Omron CX-Programmer project 新工程 (CX-Programmer 9.31)

# PLC 新PLC1: CP1E E10

## Global symbols (name address type ; comment)
0.00 BOOL  ; 输入
0.01 BOOL  ; 传感器触发正信号
0.02 BOOL  ; 复位
0.03 BOOL  ; 转盘工位传感器信号
100.00 BOOL  ; 相机触发信号
100.01 BOOL  ; 光源触发
100.02 BOOL  ; 剔除信号
100.03 BOOL  ; 设备停止1
D2 CHANNEL  ; 气缸1剔除延时调整
D8 CHANNEL  ; 气缸1剔除延时调整

## Program 新程序1 (cyclic task 0)

### Section 延时设置

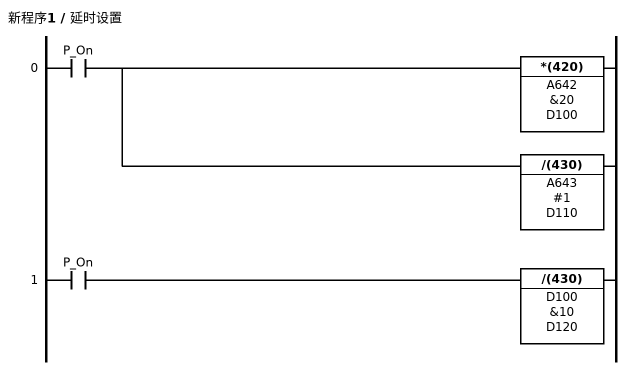
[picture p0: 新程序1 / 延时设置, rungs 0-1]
; rung 0
LD P_On
*(420) A642 &20 D100
/(430) A643 #1 D110
; rung 1
LD P_On
/(430) D100 &10 D120

### Section 相机触发

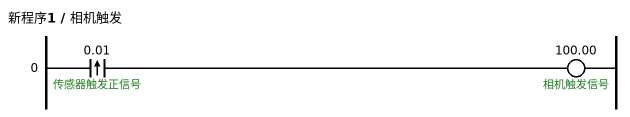
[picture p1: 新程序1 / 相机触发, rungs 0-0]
; rung 0
@LD 0.01  ; 传感器触发正信号
OUT 100.00  ; 相机触发信号

### Section 错误记忆

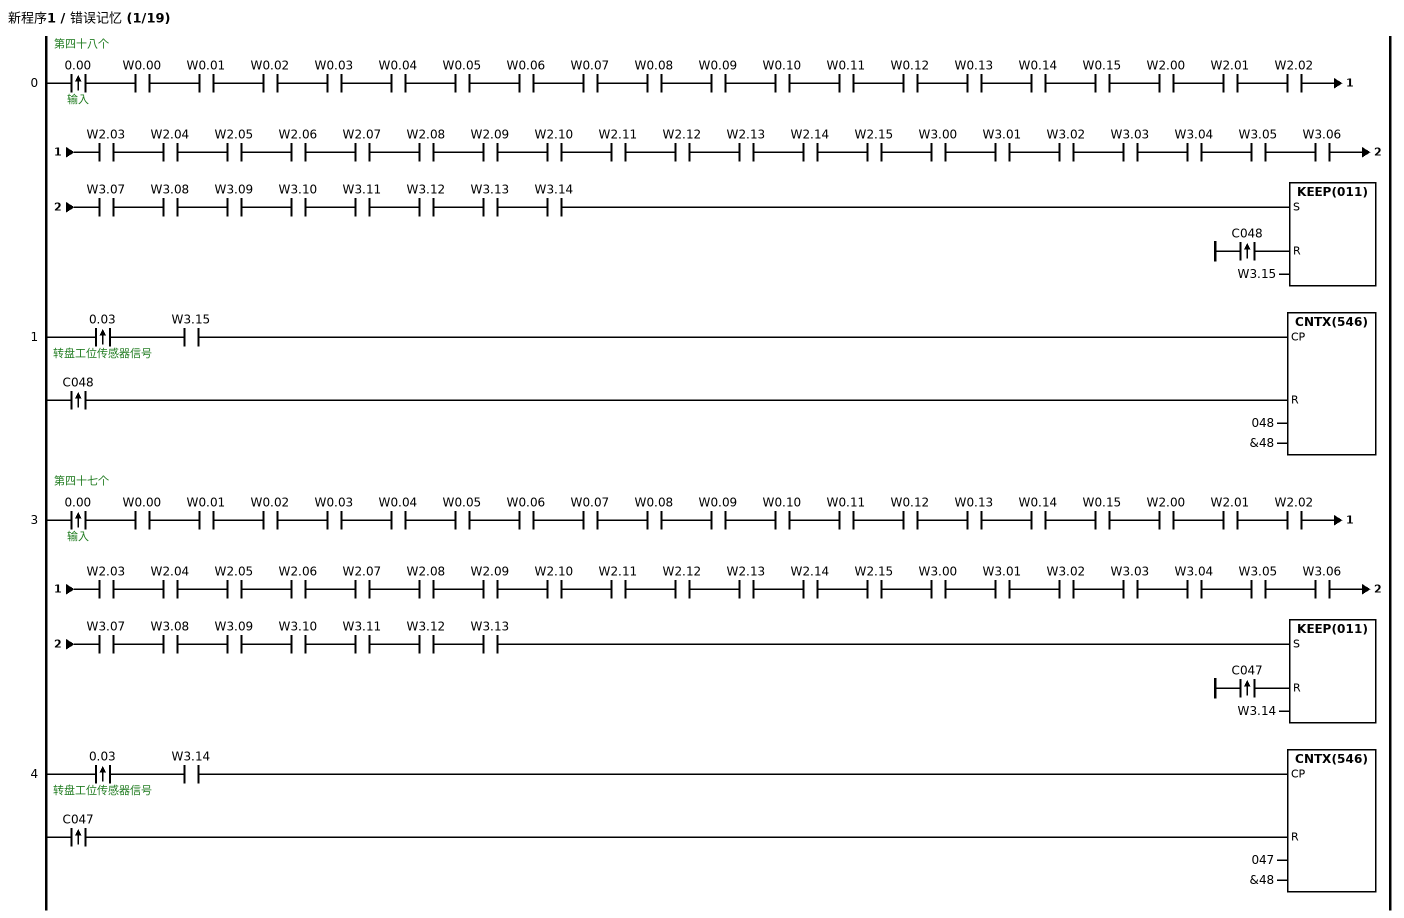
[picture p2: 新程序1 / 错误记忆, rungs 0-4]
; rung 0: 第四十八个
@LD 0.00  ; 输入
AND W0.00
AND W0.01
AND W0.02
AND W0.03
AND W0.04
AND W0.05
AND W0.06
AND W0.07
AND W0.08
AND W0.09
AND W0.10
AND W0.11
AND W0.12
AND W0.13
AND W0.14
AND W0.15
AND W2.00
AND W2.01
AND W2.02
AND W2.03
AND W2.04
AND W2.05
AND W2.06
AND W2.07
AND W2.08
AND W2.09
AND W2.10
AND W2.11
AND W2.12
AND W2.13
AND W2.14
AND W2.15
AND W3.00
AND W3.01
AND W3.02
AND W3.03
AND W3.04
AND W3.05
AND W3.06
AND W3.07
AND W3.08
AND W3.09
AND W3.10
AND W3.11
AND W3.12
AND W3.13
AND W3.14
@LD C048
KEEP(011) W3.15
; rung 1
@LD 0.03  ; 转盘工位传感器信号
AND W3.15
@LD C048
CNTX(546) 048 &48
; rung 3: 第四十七个
@LD 0.00  ; 输入
AND W0.00
AND W0.01
AND W0.02
AND W0.03
AND W0.04
AND W0.05
AND W0.06
AND W0.07
AND W0.08
AND W0.09
AND W0.10
AND W0.11
AND W0.12
AND W0.13
AND W0.14
AND W0.15
AND W2.00
AND W2.01
AND W2.02
AND W2.03
AND W2.04
AND W2.05
AND W2.06
AND W2.07
AND W2.08
AND W2.09
AND W2.10
AND W2.11
AND W2.12
AND W2.13
AND W2.14
AND W2.15
AND W3.00
AND W3.01
AND W3.02
AND W3.03
AND W3.04
AND W3.05
AND W3.06
AND W3.07
AND W3.08
AND W3.09
AND W3.10
AND W3.11
AND W3.12
AND W3.13
@LD C047
KEEP(011) W3.14
; rung 4
@LD 0.03  ; 转盘工位传感器信号
AND W3.14
@LD C047
CNTX(546) 047 &48

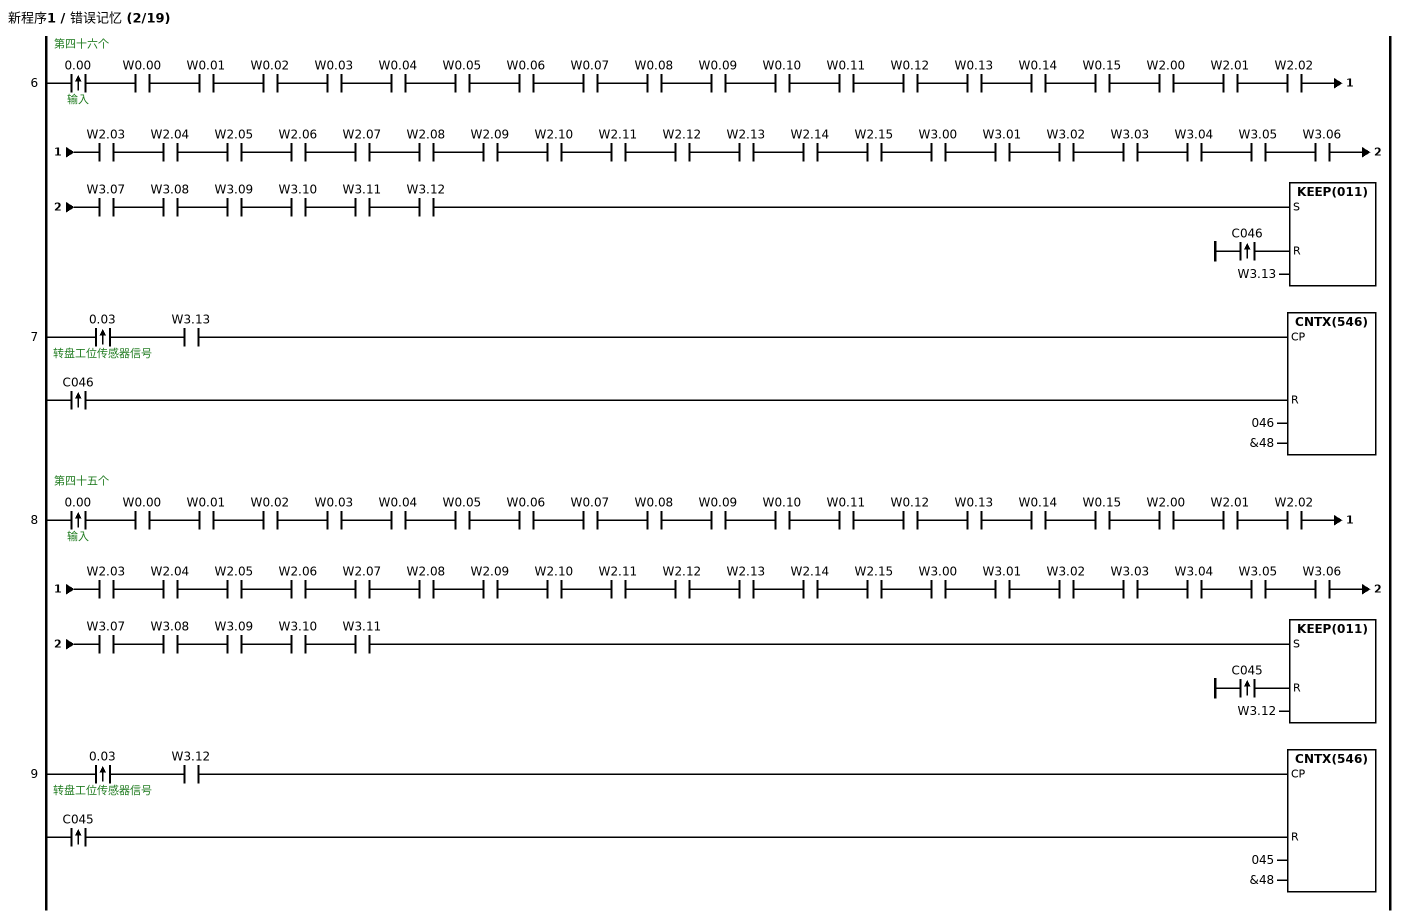
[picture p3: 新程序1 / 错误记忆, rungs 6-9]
; rung 6: 第四十六个
@LD 0.00  ; 输入
AND W0.00
AND W0.01
AND W0.02
AND W0.03
AND W0.04
AND W0.05
AND W0.06
AND W0.07
AND W0.08
AND W0.09
AND W0.10
AND W0.11
AND W0.12
AND W0.13
AND W0.14
AND W0.15
AND W2.00
AND W2.01
AND W2.02
AND W2.03
AND W2.04
AND W2.05
AND W2.06
AND W2.07
AND W2.08
AND W2.09
AND W2.10
AND W2.11
AND W2.12
AND W2.13
AND W2.14
AND W2.15
AND W3.00
AND W3.01
AND W3.02
AND W3.03
AND W3.04
AND W3.05
AND W3.06
AND W3.07
AND W3.08
AND W3.09
AND W3.10
AND W3.11
AND W3.12
@LD C046
KEEP(011) W3.13
; rung 7
@LD 0.03  ; 转盘工位传感器信号
AND W3.13
@LD C046
CNTX(546) 046 &48
; rung 8: 第四十五个
@LD 0.00  ; 输入
AND W0.00
AND W0.01
AND W0.02
AND W0.03
AND W0.04
AND W0.05
AND W0.06
AND W0.07
AND W0.08
AND W0.09
AND W0.10
AND W0.11
AND W0.12
AND W0.13
AND W0.14
AND W0.15
AND W2.00
AND W2.01
AND W2.02
AND W2.03
AND W2.04
AND W2.05
AND W2.06
AND W2.07
AND W2.08
AND W2.09
AND W2.10
AND W2.11
AND W2.12
AND W2.13
AND W2.14
AND W2.15
AND W3.00
AND W3.01
AND W3.02
AND W3.03
AND W3.04
AND W3.05
AND W3.06
AND W3.07
AND W3.08
AND W3.09
AND W3.10
AND W3.11
@LD C045
KEEP(011) W3.12
; rung 9
@LD 0.03  ; 转盘工位传感器信号
AND W3.12
@LD C045
CNTX(546) 045 &48

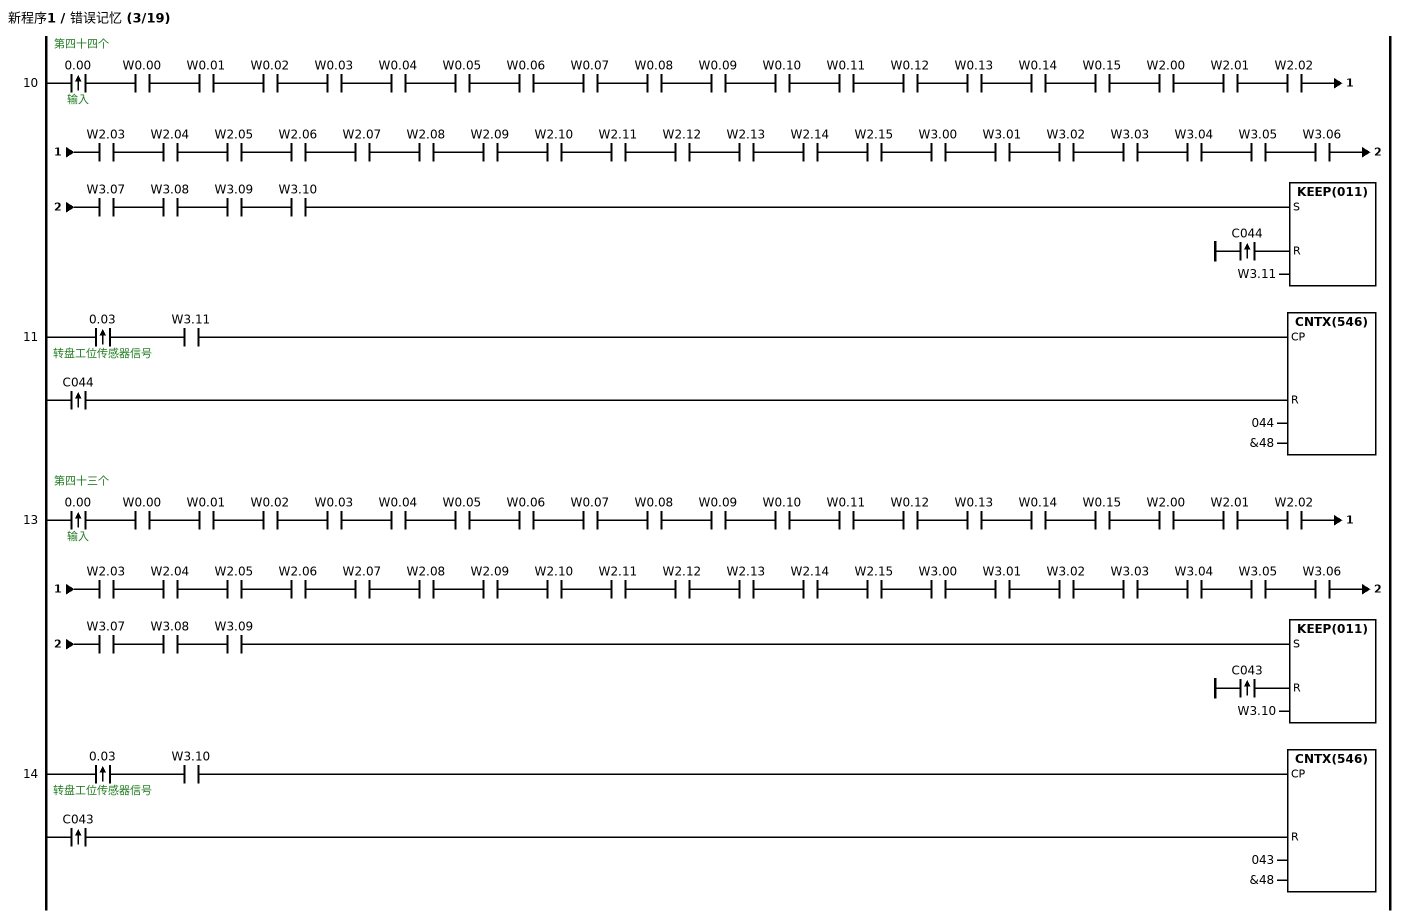
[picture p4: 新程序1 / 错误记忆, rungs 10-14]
; rung 10: 第四十四个
@LD 0.00  ; 输入
AND W0.00
AND W0.01
AND W0.02
AND W0.03
AND W0.04
AND W0.05
AND W0.06
AND W0.07
AND W0.08
AND W0.09
AND W0.10
AND W0.11
AND W0.12
AND W0.13
AND W0.14
AND W0.15
AND W2.00
AND W2.01
AND W2.02
AND W2.03
AND W2.04
AND W2.05
AND W2.06
AND W2.07
AND W2.08
AND W2.09
AND W2.10
AND W2.11
AND W2.12
AND W2.13
AND W2.14
AND W2.15
AND W3.00
AND W3.01
AND W3.02
AND W3.03
AND W3.04
AND W3.05
AND W3.06
AND W3.07
AND W3.08
AND W3.09
AND W3.10
@LD C044
KEEP(011) W3.11
; rung 11
@LD 0.03  ; 转盘工位传感器信号
AND W3.11
@LD C044
CNTX(546) 044 &48
; rung 13: 第四十三个
@LD 0.00  ; 输入
AND W0.00
AND W0.01
AND W0.02
AND W0.03
AND W0.04
AND W0.05
AND W0.06
AND W0.07
AND W0.08
AND W0.09
AND W0.10
AND W0.11
AND W0.12
AND W0.13
AND W0.14
AND W0.15
AND W2.00
AND W2.01
AND W2.02
AND W2.03
AND W2.04
AND W2.05
AND W2.06
AND W2.07
AND W2.08
AND W2.09
AND W2.10
AND W2.11
AND W2.12
AND W2.13
AND W2.14
AND W2.15
AND W3.00
AND W3.01
AND W3.02
AND W3.03
AND W3.04
AND W3.05
AND W3.06
AND W3.07
AND W3.08
AND W3.09
@LD C043
KEEP(011) W3.10
; rung 14
@LD 0.03  ; 转盘工位传感器信号
AND W3.10
@LD C043
CNTX(546) 043 &48

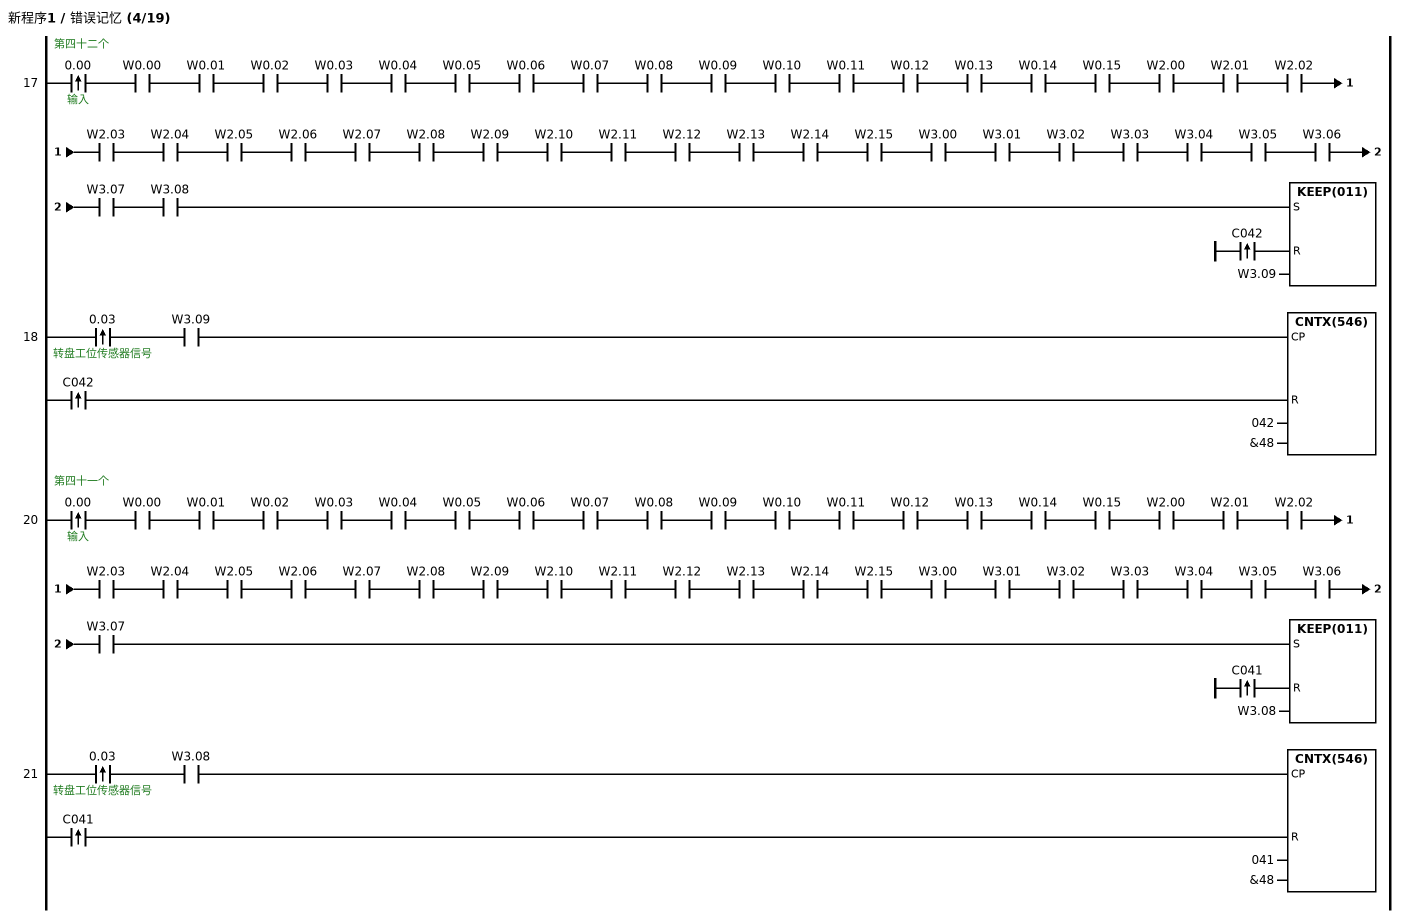
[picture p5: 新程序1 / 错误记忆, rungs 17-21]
; rung 17: 第四十二个
@LD 0.00  ; 输入
AND W0.00
AND W0.01
AND W0.02
AND W0.03
AND W0.04
AND W0.05
AND W0.06
AND W0.07
AND W0.08
AND W0.09
AND W0.10
AND W0.11
AND W0.12
AND W0.13
AND W0.14
AND W0.15
AND W2.00
AND W2.01
AND W2.02
AND W2.03
AND W2.04
AND W2.05
AND W2.06
AND W2.07
AND W2.08
AND W2.09
AND W2.10
AND W2.11
AND W2.12
AND W2.13
AND W2.14
AND W2.15
AND W3.00
AND W3.01
AND W3.02
AND W3.03
AND W3.04
AND W3.05
AND W3.06
AND W3.07
AND W3.08
@LD C042
KEEP(011) W3.09
; rung 18
@LD 0.03  ; 转盘工位传感器信号
AND W3.09
@LD C042
CNTX(546) 042 &48
; rung 20: 第四十一个
@LD 0.00  ; 输入
AND W0.00
AND W0.01
AND W0.02
AND W0.03
AND W0.04
AND W0.05
AND W0.06
AND W0.07
AND W0.08
AND W0.09
AND W0.10
AND W0.11
AND W0.12
AND W0.13
AND W0.14
AND W0.15
AND W2.00
AND W2.01
AND W2.02
AND W2.03
AND W2.04
AND W2.05
AND W2.06
AND W2.07
AND W2.08
AND W2.09
AND W2.10
AND W2.11
AND W2.12
AND W2.13
AND W2.14
AND W2.15
AND W3.00
AND W3.01
AND W3.02
AND W3.03
AND W3.04
AND W3.05
AND W3.06
AND W3.07
@LD C041
KEEP(011) W3.08
; rung 21
@LD 0.03  ; 转盘工位传感器信号
AND W3.08
@LD C041
CNTX(546) 041 &48

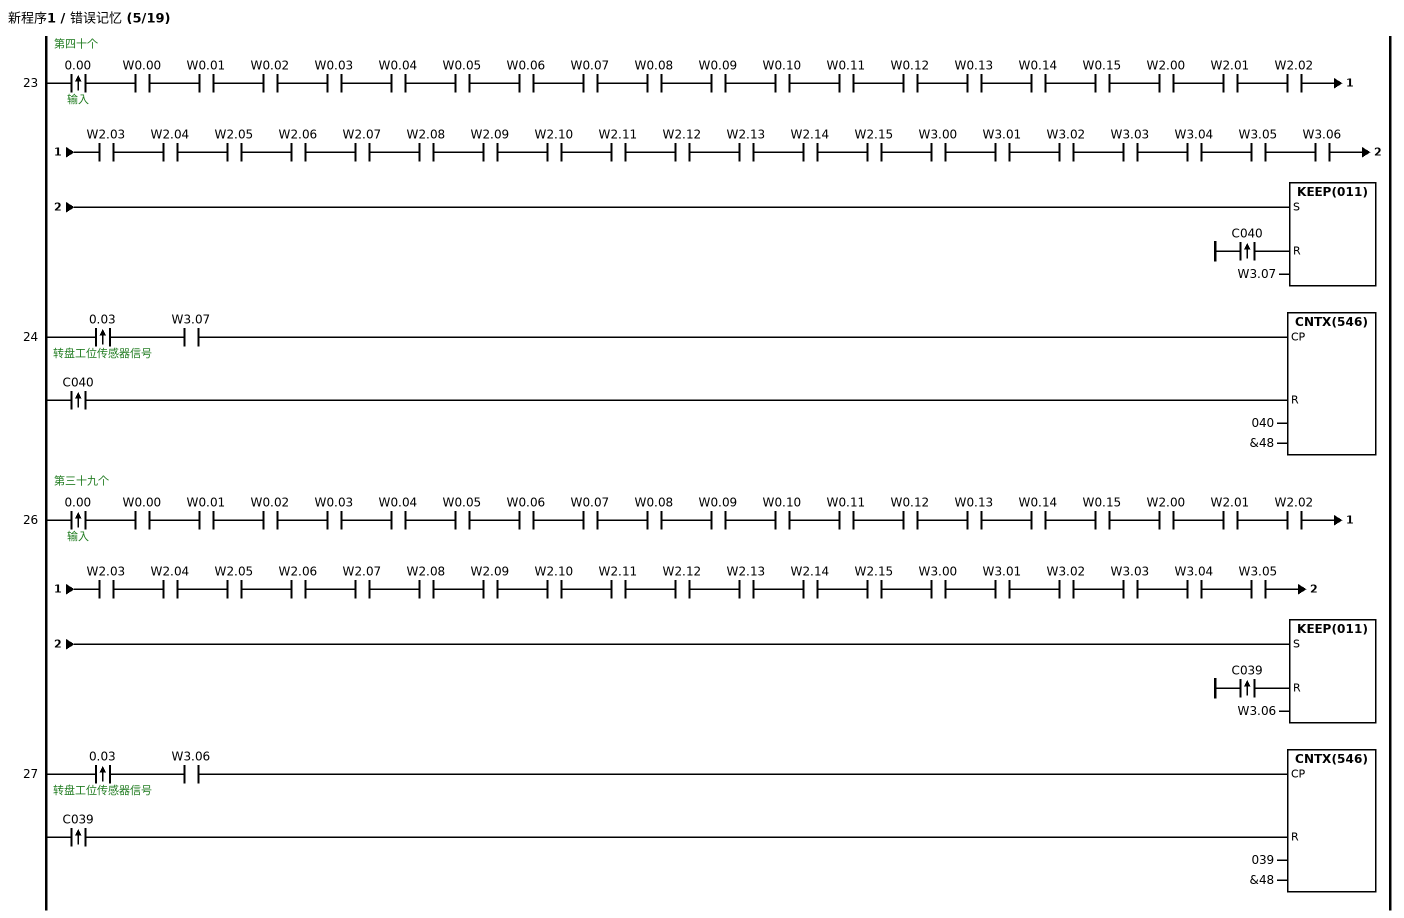
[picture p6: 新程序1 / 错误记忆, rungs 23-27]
; rung 23: 第四十个
@LD 0.00  ; 输入
AND W0.00
AND W0.01
AND W0.02
AND W0.03
AND W0.04
AND W0.05
AND W0.06
AND W0.07
AND W0.08
AND W0.09
AND W0.10
AND W0.11
AND W0.12
AND W0.13
AND W0.14
AND W0.15
AND W2.00
AND W2.01
AND W2.02
AND W2.03
AND W2.04
AND W2.05
AND W2.06
AND W2.07
AND W2.08
AND W2.09
AND W2.10
AND W2.11
AND W2.12
AND W2.13
AND W2.14
AND W2.15
AND W3.00
AND W3.01
AND W3.02
AND W3.03
AND W3.04
AND W3.05
AND W3.06
@LD C040
KEEP(011) W3.07
; rung 24
@LD 0.03  ; 转盘工位传感器信号
AND W3.07
@LD C040
CNTX(546) 040 &48
; rung 26: 第三十九个
@LD 0.00  ; 输入
AND W0.00
AND W0.01
AND W0.02
AND W0.03
AND W0.04
AND W0.05
AND W0.06
AND W0.07
AND W0.08
AND W0.09
AND W0.10
AND W0.11
AND W0.12
AND W0.13
AND W0.14
AND W0.15
AND W2.00
AND W2.01
AND W2.02
AND W2.03
AND W2.04
AND W2.05
AND W2.06
AND W2.07
AND W2.08
AND W2.09
AND W2.10
AND W2.11
AND W2.12
AND W2.13
AND W2.14
AND W2.15
AND W3.00
AND W3.01
AND W3.02
AND W3.03
AND W3.04
AND W3.05
@LD C039
KEEP(011) W3.06
; rung 27
@LD 0.03  ; 转盘工位传感器信号
AND W3.06
@LD C039
CNTX(546) 039 &48

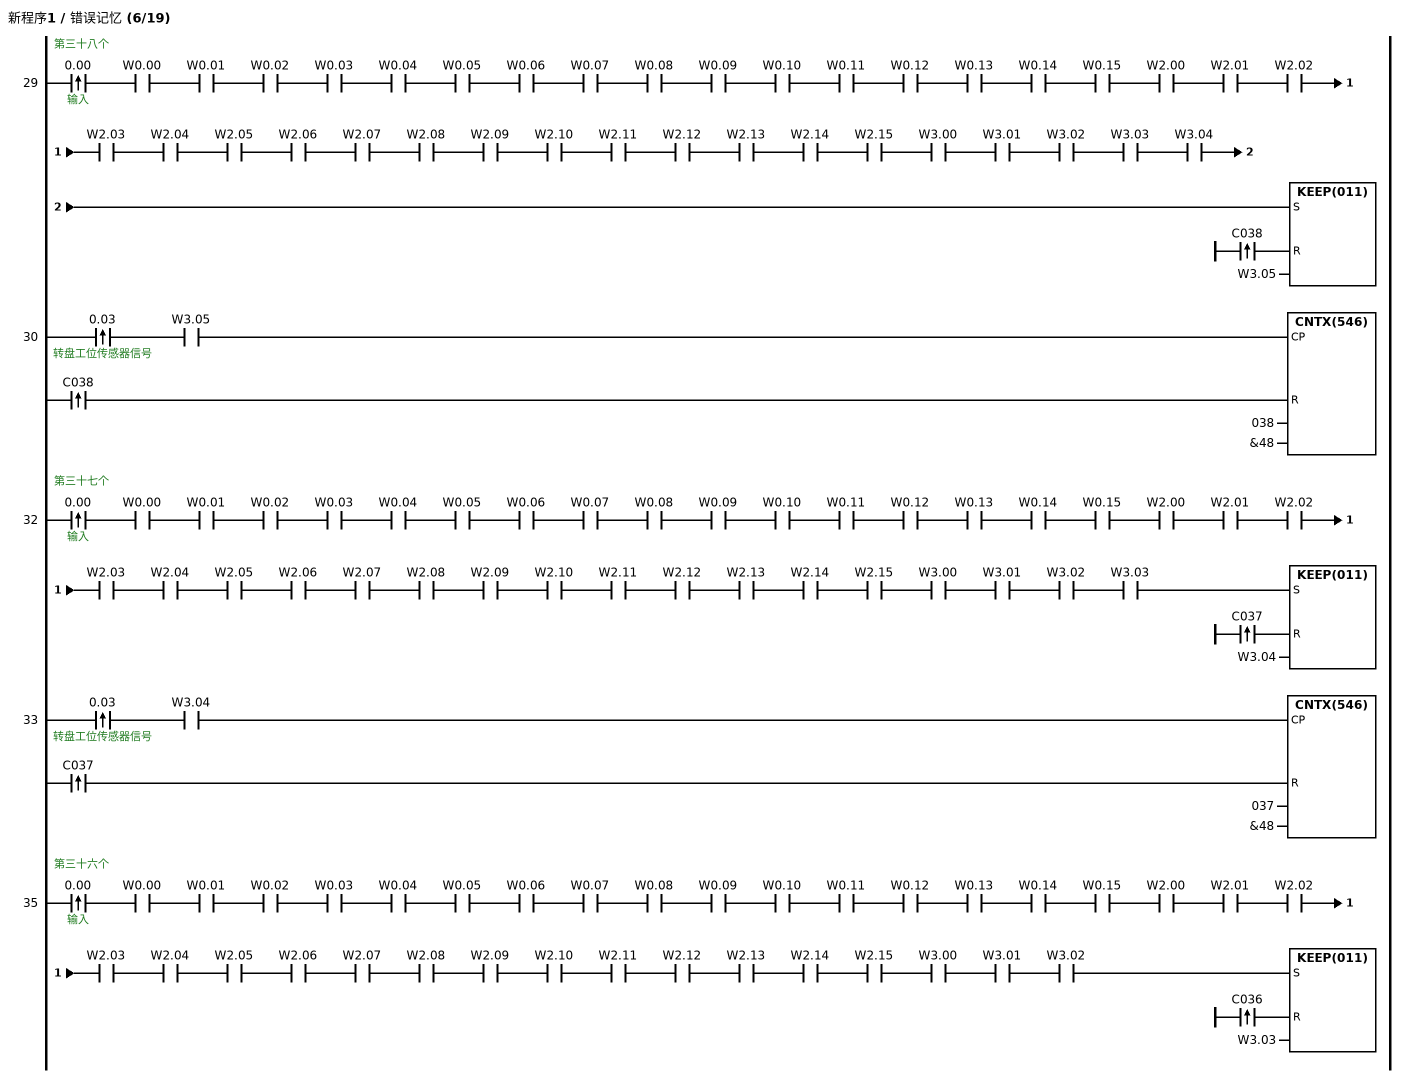
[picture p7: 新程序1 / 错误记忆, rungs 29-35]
; rung 29: 第三十八个
@LD 0.00  ; 输入
AND W0.00
AND W0.01
AND W0.02
AND W0.03
AND W0.04
AND W0.05
AND W0.06
AND W0.07
AND W0.08
AND W0.09
AND W0.10
AND W0.11
AND W0.12
AND W0.13
AND W0.14
AND W0.15
AND W2.00
AND W2.01
AND W2.02
AND W2.03
AND W2.04
AND W2.05
AND W2.06
AND W2.07
AND W2.08
AND W2.09
AND W2.10
AND W2.11
AND W2.12
AND W2.13
AND W2.14
AND W2.15
AND W3.00
AND W3.01
AND W3.02
AND W3.03
AND W3.04
@LD C038
KEEP(011) W3.05
; rung 30
@LD 0.03  ; 转盘工位传感器信号
AND W3.05
@LD C038
CNTX(546) 038 &48
; rung 32: 第三十七个
@LD 0.00  ; 输入
AND W0.00
AND W0.01
AND W0.02
AND W0.03
AND W0.04
AND W0.05
AND W0.06
AND W0.07
AND W0.08
AND W0.09
AND W0.10
AND W0.11
AND W0.12
AND W0.13
AND W0.14
AND W0.15
AND W2.00
AND W2.01
AND W2.02
AND W2.03
AND W2.04
AND W2.05
AND W2.06
AND W2.07
AND W2.08
AND W2.09
AND W2.10
AND W2.11
AND W2.12
AND W2.13
AND W2.14
AND W2.15
AND W3.00
AND W3.01
AND W3.02
AND W3.03
@LD C037
KEEP(011) W3.04
; rung 33
@LD 0.03  ; 转盘工位传感器信号
AND W3.04
@LD C037
CNTX(546) 037 &48
; rung 35: 第三十六个
@LD 0.00  ; 输入
AND W0.00
AND W0.01
AND W0.02
AND W0.03
AND W0.04
AND W0.05
AND W0.06
AND W0.07
AND W0.08
AND W0.09
AND W0.10
AND W0.11
AND W0.12
AND W0.13
AND W0.14
AND W0.15
AND W2.00
AND W2.01
AND W2.02
AND W2.03
AND W2.04
AND W2.05
AND W2.06
AND W2.07
AND W2.08
AND W2.09
AND W2.10
AND W2.11
AND W2.12
AND W2.13
AND W2.14
AND W2.15
AND W3.00
AND W3.01
AND W3.02
@LD C036
KEEP(011) W3.03

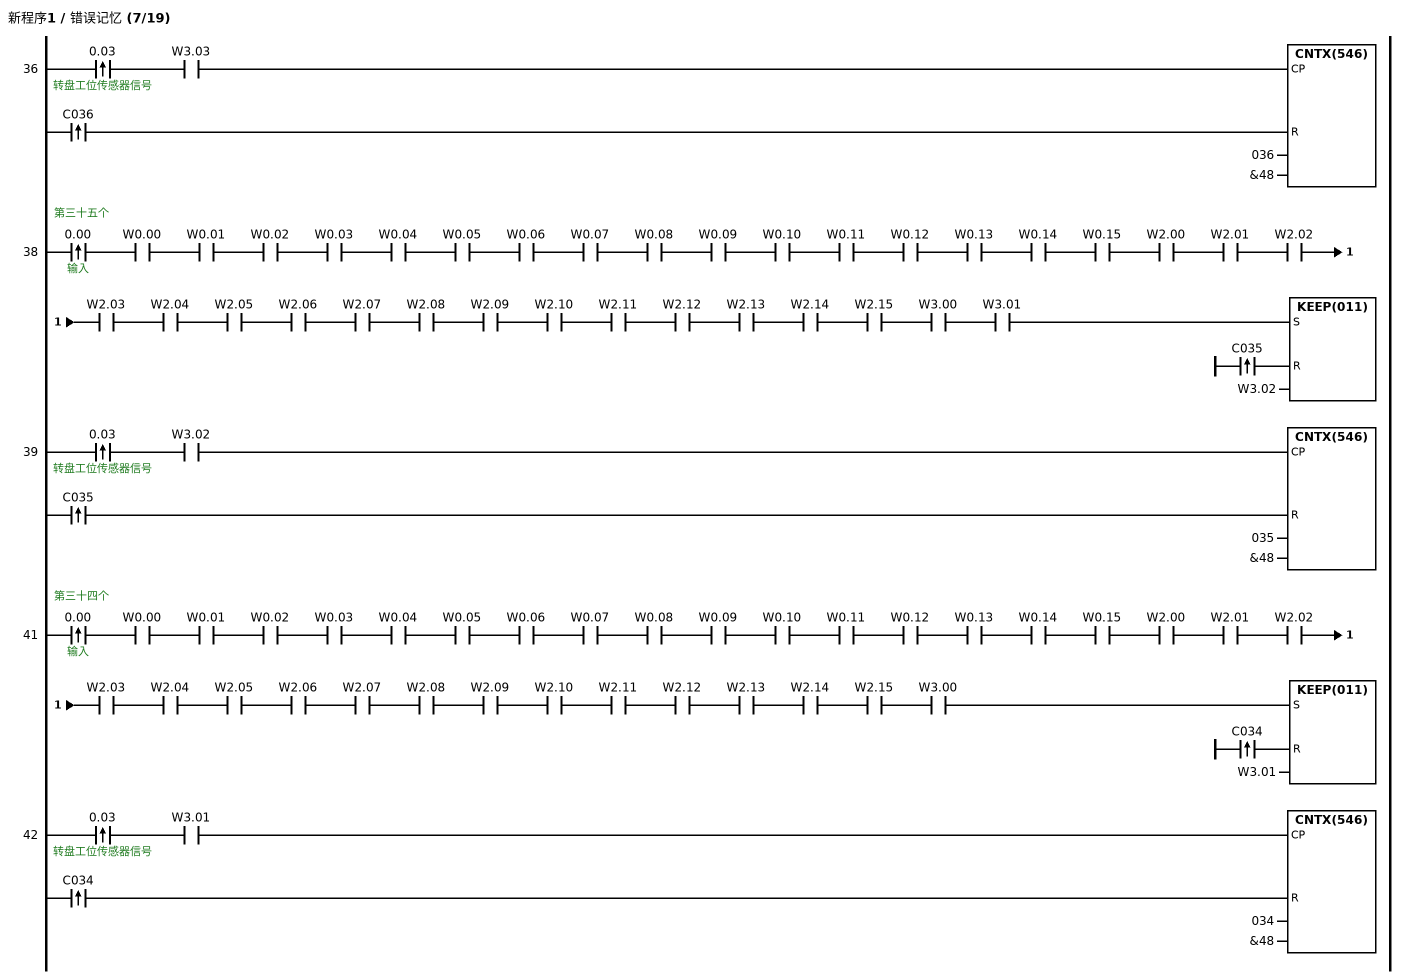
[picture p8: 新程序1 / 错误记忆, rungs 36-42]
; rung 36
@LD 0.03  ; 转盘工位传感器信号
AND W3.03
@LD C036
CNTX(546) 036 &48
; rung 38: 第三十五个
@LD 0.00  ; 输入
AND W0.00
AND W0.01
AND W0.02
AND W0.03
AND W0.04
AND W0.05
AND W0.06
AND W0.07
AND W0.08
AND W0.09
AND W0.10
AND W0.11
AND W0.12
AND W0.13
AND W0.14
AND W0.15
AND W2.00
AND W2.01
AND W2.02
AND W2.03
AND W2.04
AND W2.05
AND W2.06
AND W2.07
AND W2.08
AND W2.09
AND W2.10
AND W2.11
AND W2.12
AND W2.13
AND W2.14
AND W2.15
AND W3.00
AND W3.01
@LD C035
KEEP(011) W3.02
; rung 39
@LD 0.03  ; 转盘工位传感器信号
AND W3.02
@LD C035
CNTX(546) 035 &48
; rung 41: 第三十四个
@LD 0.00  ; 输入
AND W0.00
AND W0.01
AND W0.02
AND W0.03
AND W0.04
AND W0.05
AND W0.06
AND W0.07
AND W0.08
AND W0.09
AND W0.10
AND W0.11
AND W0.12
AND W0.13
AND W0.14
AND W0.15
AND W2.00
AND W2.01
AND W2.02
AND W2.03
AND W2.04
AND W2.05
AND W2.06
AND W2.07
AND W2.08
AND W2.09
AND W2.10
AND W2.11
AND W2.12
AND W2.13
AND W2.14
AND W2.15
AND W3.00
@LD C034
KEEP(011) W3.01
; rung 42
@LD 0.03  ; 转盘工位传感器信号
AND W3.01
@LD C034
CNTX(546) 034 &48

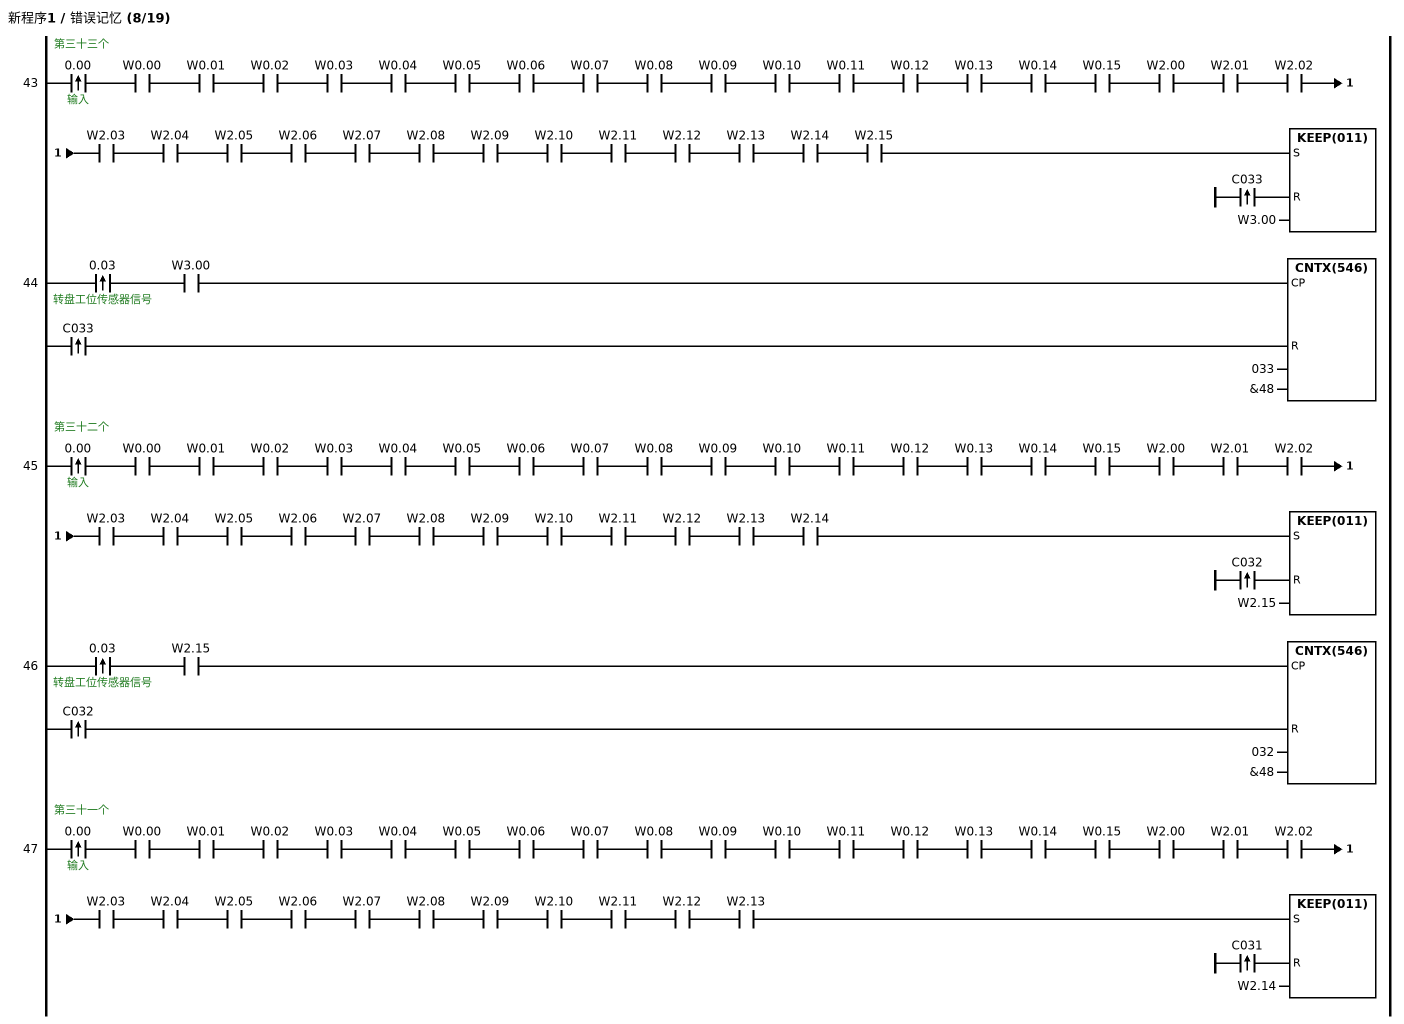
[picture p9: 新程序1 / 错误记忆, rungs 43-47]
; rung 43: 第三十三个
@LD 0.00  ; 输入
AND W0.00
AND W0.01
AND W0.02
AND W0.03
AND W0.04
AND W0.05
AND W0.06
AND W0.07
AND W0.08
AND W0.09
AND W0.10
AND W0.11
AND W0.12
AND W0.13
AND W0.14
AND W0.15
AND W2.00
AND W2.01
AND W2.02
AND W2.03
AND W2.04
AND W2.05
AND W2.06
AND W2.07
AND W2.08
AND W2.09
AND W2.10
AND W2.11
AND W2.12
AND W2.13
AND W2.14
AND W2.15
@LD C033
KEEP(011) W3.00
; rung 44
@LD 0.03  ; 转盘工位传感器信号
AND W3.00
@LD C033
CNTX(546) 033 &48
; rung 45: 第三十二个
@LD 0.00  ; 输入
AND W0.00
AND W0.01
AND W0.02
AND W0.03
AND W0.04
AND W0.05
AND W0.06
AND W0.07
AND W0.08
AND W0.09
AND W0.10
AND W0.11
AND W0.12
AND W0.13
AND W0.14
AND W0.15
AND W2.00
AND W2.01
AND W2.02
AND W2.03
AND W2.04
AND W2.05
AND W2.06
AND W2.07
AND W2.08
AND W2.09
AND W2.10
AND W2.11
AND W2.12
AND W2.13
AND W2.14
@LD C032
KEEP(011) W2.15
; rung 46
@LD 0.03  ; 转盘工位传感器信号
AND W2.15
@LD C032
CNTX(546) 032 &48
; rung 47: 第三十一个
@LD 0.00  ; 输入
AND W0.00
AND W0.01
AND W0.02
AND W0.03
AND W0.04
AND W0.05
AND W0.06
AND W0.07
AND W0.08
AND W0.09
AND W0.10
AND W0.11
AND W0.12
AND W0.13
AND W0.14
AND W0.15
AND W2.00
AND W2.01
AND W2.02
AND W2.03
AND W2.04
AND W2.05
AND W2.06
AND W2.07
AND W2.08
AND W2.09
AND W2.10
AND W2.11
AND W2.12
AND W2.13
@LD C031
KEEP(011) W2.14

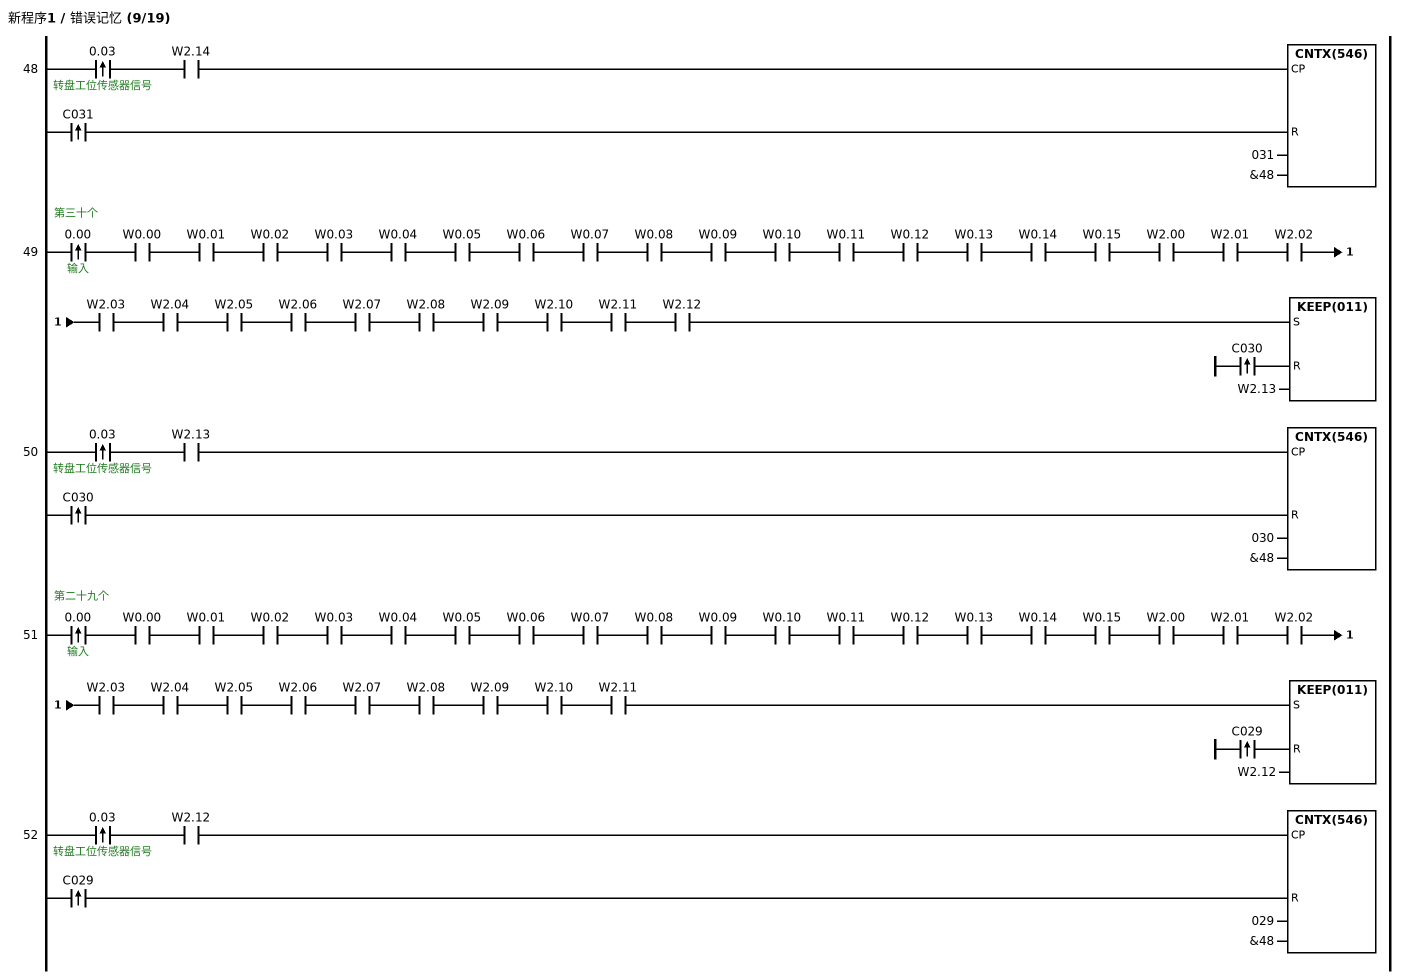
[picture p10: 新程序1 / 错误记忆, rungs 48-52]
; rung 48
@LD 0.03  ; 转盘工位传感器信号
AND W2.14
@LD C031
CNTX(546) 031 &48
; rung 49: 第三十个
@LD 0.00  ; 输入
AND W0.00
AND W0.01
AND W0.02
AND W0.03
AND W0.04
AND W0.05
AND W0.06
AND W0.07
AND W0.08
AND W0.09
AND W0.10
AND W0.11
AND W0.12
AND W0.13
AND W0.14
AND W0.15
AND W2.00
AND W2.01
AND W2.02
AND W2.03
AND W2.04
AND W2.05
AND W2.06
AND W2.07
AND W2.08
AND W2.09
AND W2.10
AND W2.11
AND W2.12
@LD C030
KEEP(011) W2.13
; rung 50
@LD 0.03  ; 转盘工位传感器信号
AND W2.13
@LD C030
CNTX(546) 030 &48
; rung 51: 第二十九个
@LD 0.00  ; 输入
AND W0.00
AND W0.01
AND W0.02
AND W0.03
AND W0.04
AND W0.05
AND W0.06
AND W0.07
AND W0.08
AND W0.09
AND W0.10
AND W0.11
AND W0.12
AND W0.13
AND W0.14
AND W0.15
AND W2.00
AND W2.01
AND W2.02
AND W2.03
AND W2.04
AND W2.05
AND W2.06
AND W2.07
AND W2.08
AND W2.09
AND W2.10
AND W2.11
@LD C029
KEEP(011) W2.12
; rung 52
@LD 0.03  ; 转盘工位传感器信号
AND W2.12
@LD C029
CNTX(546) 029 &48

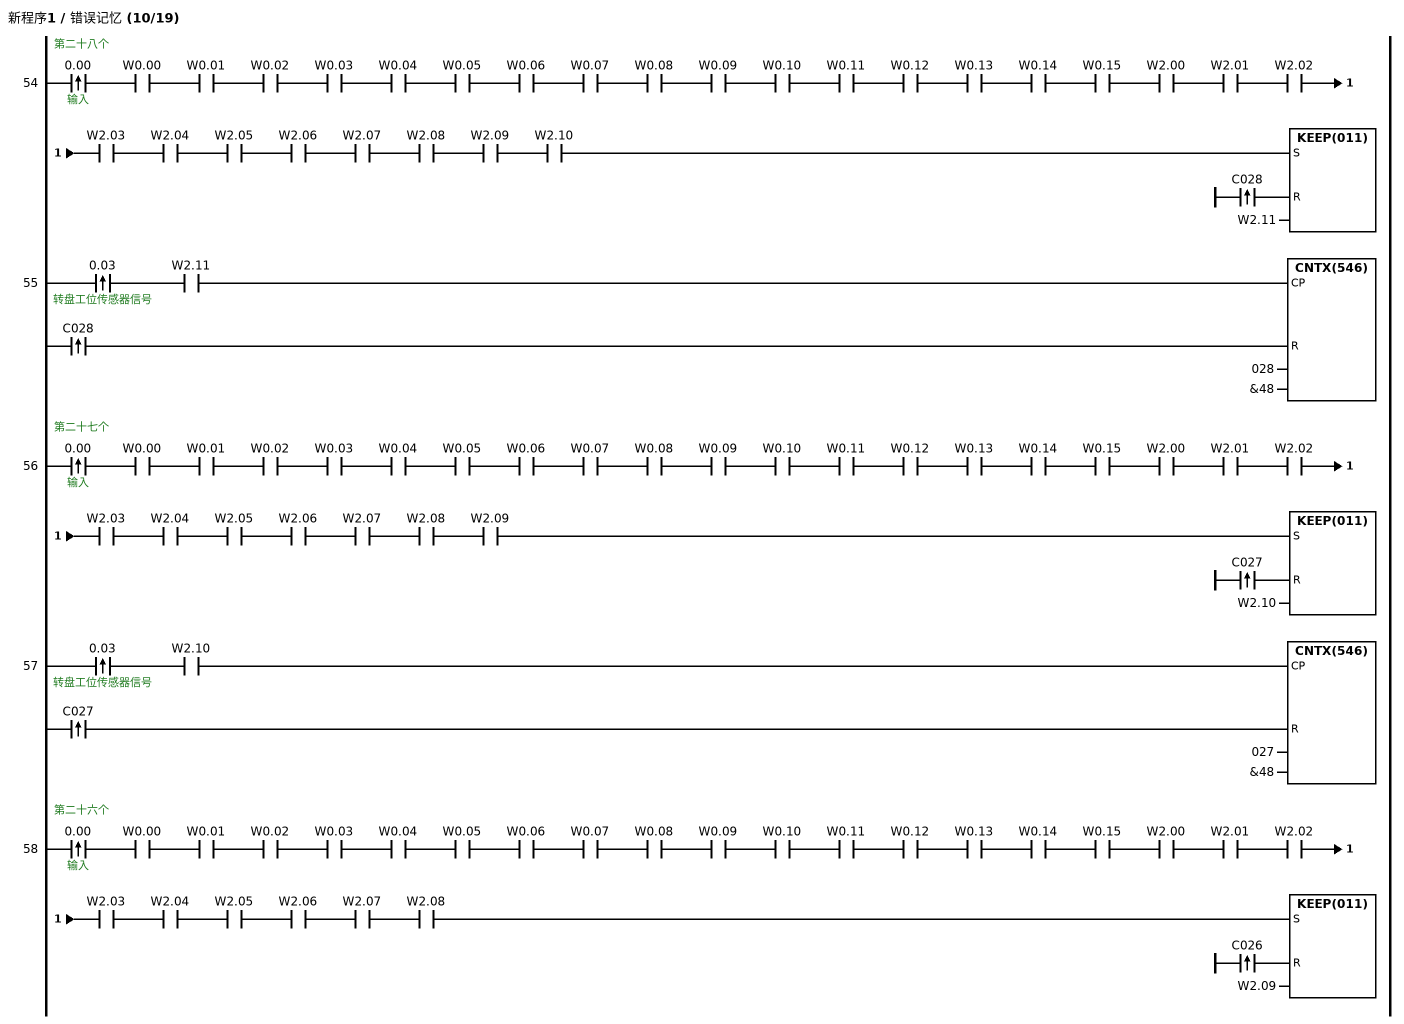
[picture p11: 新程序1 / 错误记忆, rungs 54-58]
; rung 54: 第二十八个
@LD 0.00  ; 输入
AND W0.00
AND W0.01
AND W0.02
AND W0.03
AND W0.04
AND W0.05
AND W0.06
AND W0.07
AND W0.08
AND W0.09
AND W0.10
AND W0.11
AND W0.12
AND W0.13
AND W0.14
AND W0.15
AND W2.00
AND W2.01
AND W2.02
AND W2.03
AND W2.04
AND W2.05
AND W2.06
AND W2.07
AND W2.08
AND W2.09
AND W2.10
@LD C028
KEEP(011) W2.11
; rung 55
@LD 0.03  ; 转盘工位传感器信号
AND W2.11
@LD C028
CNTX(546) 028 &48
; rung 56: 第二十七个
@LD 0.00  ; 输入
AND W0.00
AND W0.01
AND W0.02
AND W0.03
AND W0.04
AND W0.05
AND W0.06
AND W0.07
AND W0.08
AND W0.09
AND W0.10
AND W0.11
AND W0.12
AND W0.13
AND W0.14
AND W0.15
AND W2.00
AND W2.01
AND W2.02
AND W2.03
AND W2.04
AND W2.05
AND W2.06
AND W2.07
AND W2.08
AND W2.09
@LD C027
KEEP(011) W2.10
; rung 57
@LD 0.03  ; 转盘工位传感器信号
AND W2.10
@LD C027
CNTX(546) 027 &48
; rung 58: 第二十六个
@LD 0.00  ; 输入
AND W0.00
AND W0.01
AND W0.02
AND W0.03
AND W0.04
AND W0.05
AND W0.06
AND W0.07
AND W0.08
AND W0.09
AND W0.10
AND W0.11
AND W0.12
AND W0.13
AND W0.14
AND W0.15
AND W2.00
AND W2.01
AND W2.02
AND W2.03
AND W2.04
AND W2.05
AND W2.06
AND W2.07
AND W2.08
@LD C026
KEEP(011) W2.09

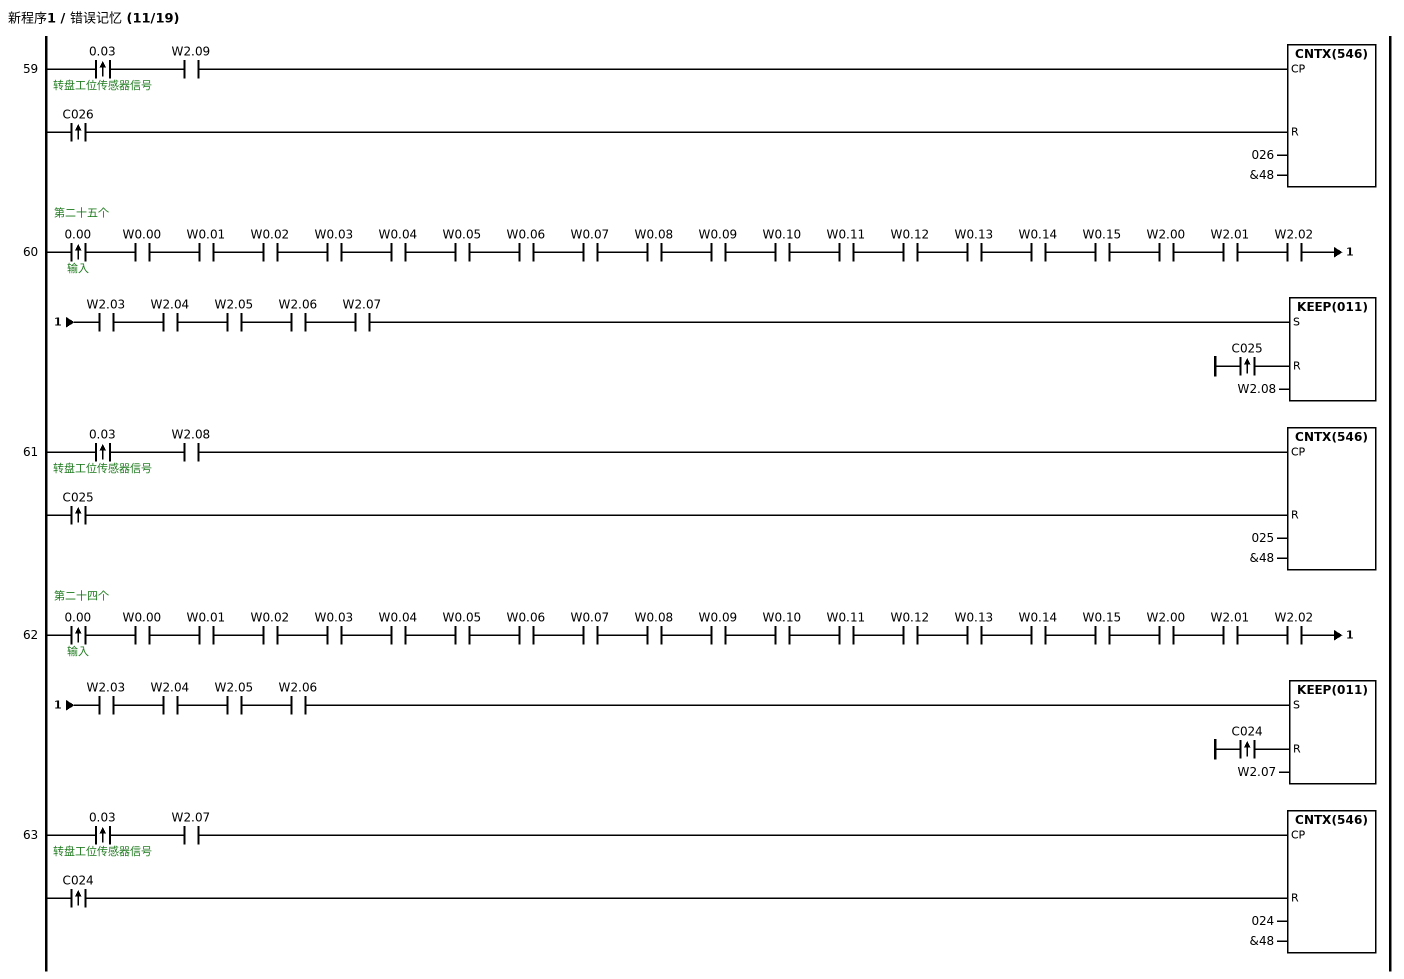
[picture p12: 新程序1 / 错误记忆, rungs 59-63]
; rung 59
@LD 0.03  ; 转盘工位传感器信号
AND W2.09
@LD C026
CNTX(546) 026 &48
; rung 60: 第二十五个
@LD 0.00  ; 输入
AND W0.00
AND W0.01
AND W0.02
AND W0.03
AND W0.04
AND W0.05
AND W0.06
AND W0.07
AND W0.08
AND W0.09
AND W0.10
AND W0.11
AND W0.12
AND W0.13
AND W0.14
AND W0.15
AND W2.00
AND W2.01
AND W2.02
AND W2.03
AND W2.04
AND W2.05
AND W2.06
AND W2.07
@LD C025
KEEP(011) W2.08
; rung 61
@LD 0.03  ; 转盘工位传感器信号
AND W2.08
@LD C025
CNTX(546) 025 &48
; rung 62: 第二十四个
@LD 0.00  ; 输入
AND W0.00
AND W0.01
AND W0.02
AND W0.03
AND W0.04
AND W0.05
AND W0.06
AND W0.07
AND W0.08
AND W0.09
AND W0.10
AND W0.11
AND W0.12
AND W0.13
AND W0.14
AND W0.15
AND W2.00
AND W2.01
AND W2.02
AND W2.03
AND W2.04
AND W2.05
AND W2.06
@LD C024
KEEP(011) W2.07
; rung 63
@LD 0.03  ; 转盘工位传感器信号
AND W2.07
@LD C024
CNTX(546) 024 &48

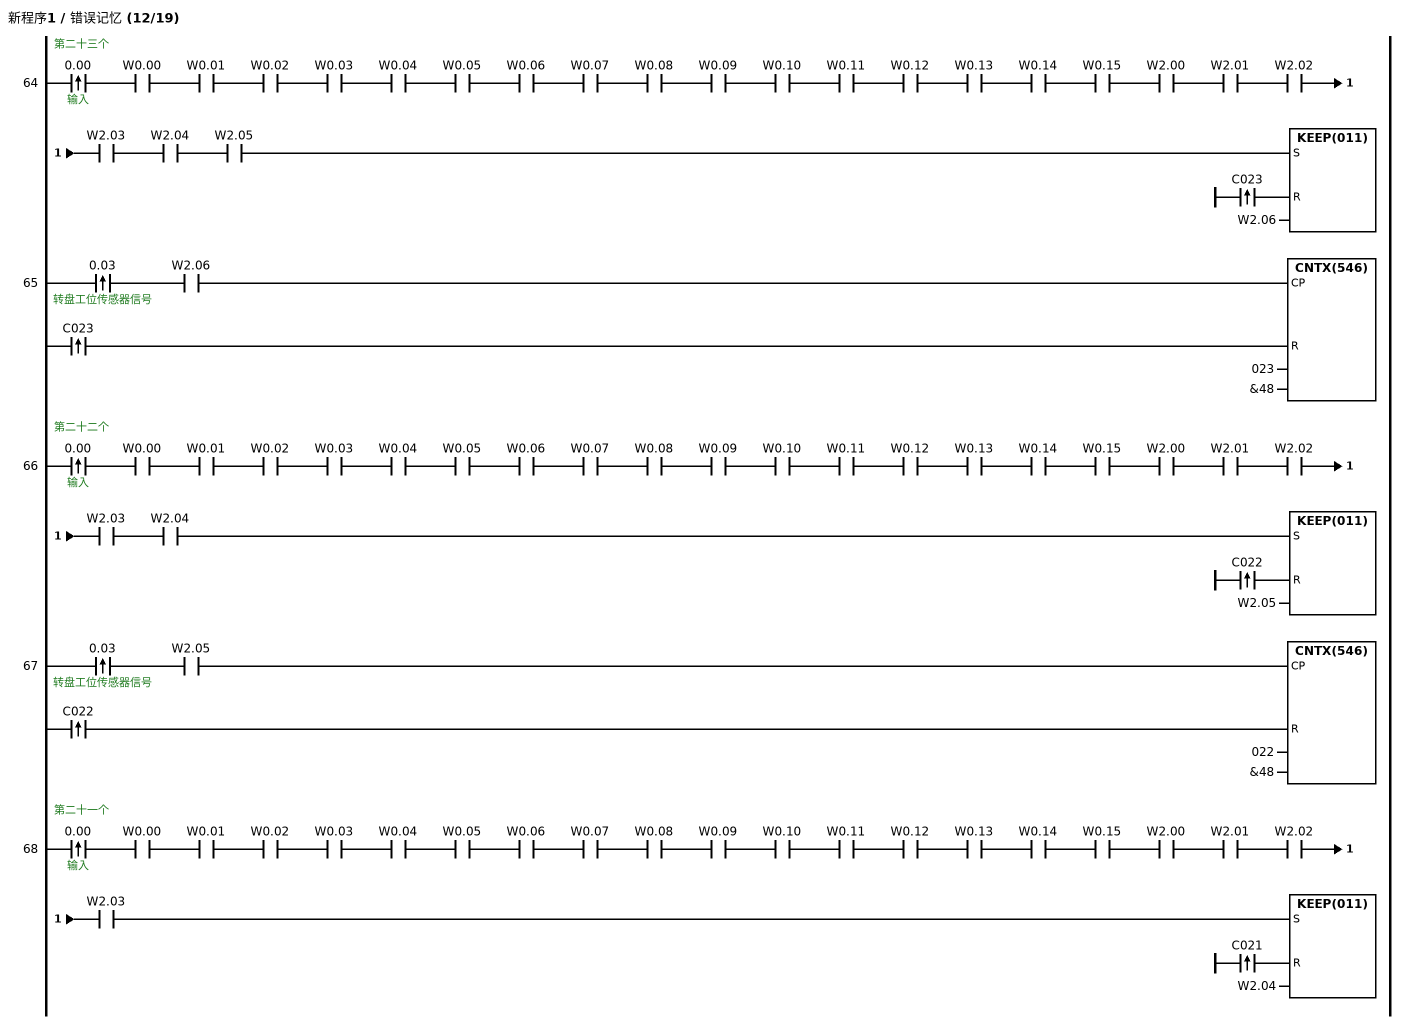
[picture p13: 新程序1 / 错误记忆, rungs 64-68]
; rung 64: 第二十三个
@LD 0.00  ; 输入
AND W0.00
AND W0.01
AND W0.02
AND W0.03
AND W0.04
AND W0.05
AND W0.06
AND W0.07
AND W0.08
AND W0.09
AND W0.10
AND W0.11
AND W0.12
AND W0.13
AND W0.14
AND W0.15
AND W2.00
AND W2.01
AND W2.02
AND W2.03
AND W2.04
AND W2.05
@LD C023
KEEP(011) W2.06
; rung 65
@LD 0.03  ; 转盘工位传感器信号
AND W2.06
@LD C023
CNTX(546) 023 &48
; rung 66: 第二十二个
@LD 0.00  ; 输入
AND W0.00
AND W0.01
AND W0.02
AND W0.03
AND W0.04
AND W0.05
AND W0.06
AND W0.07
AND W0.08
AND W0.09
AND W0.10
AND W0.11
AND W0.12
AND W0.13
AND W0.14
AND W0.15
AND W2.00
AND W2.01
AND W2.02
AND W2.03
AND W2.04
@LD C022
KEEP(011) W2.05
; rung 67
@LD 0.03  ; 转盘工位传感器信号
AND W2.05
@LD C022
CNTX(546) 022 &48
; rung 68: 第二十一个
@LD 0.00  ; 输入
AND W0.00
AND W0.01
AND W0.02
AND W0.03
AND W0.04
AND W0.05
AND W0.06
AND W0.07
AND W0.08
AND W0.09
AND W0.10
AND W0.11
AND W0.12
AND W0.13
AND W0.14
AND W0.15
AND W2.00
AND W2.01
AND W2.02
AND W2.03
@LD C021
KEEP(011) W2.04

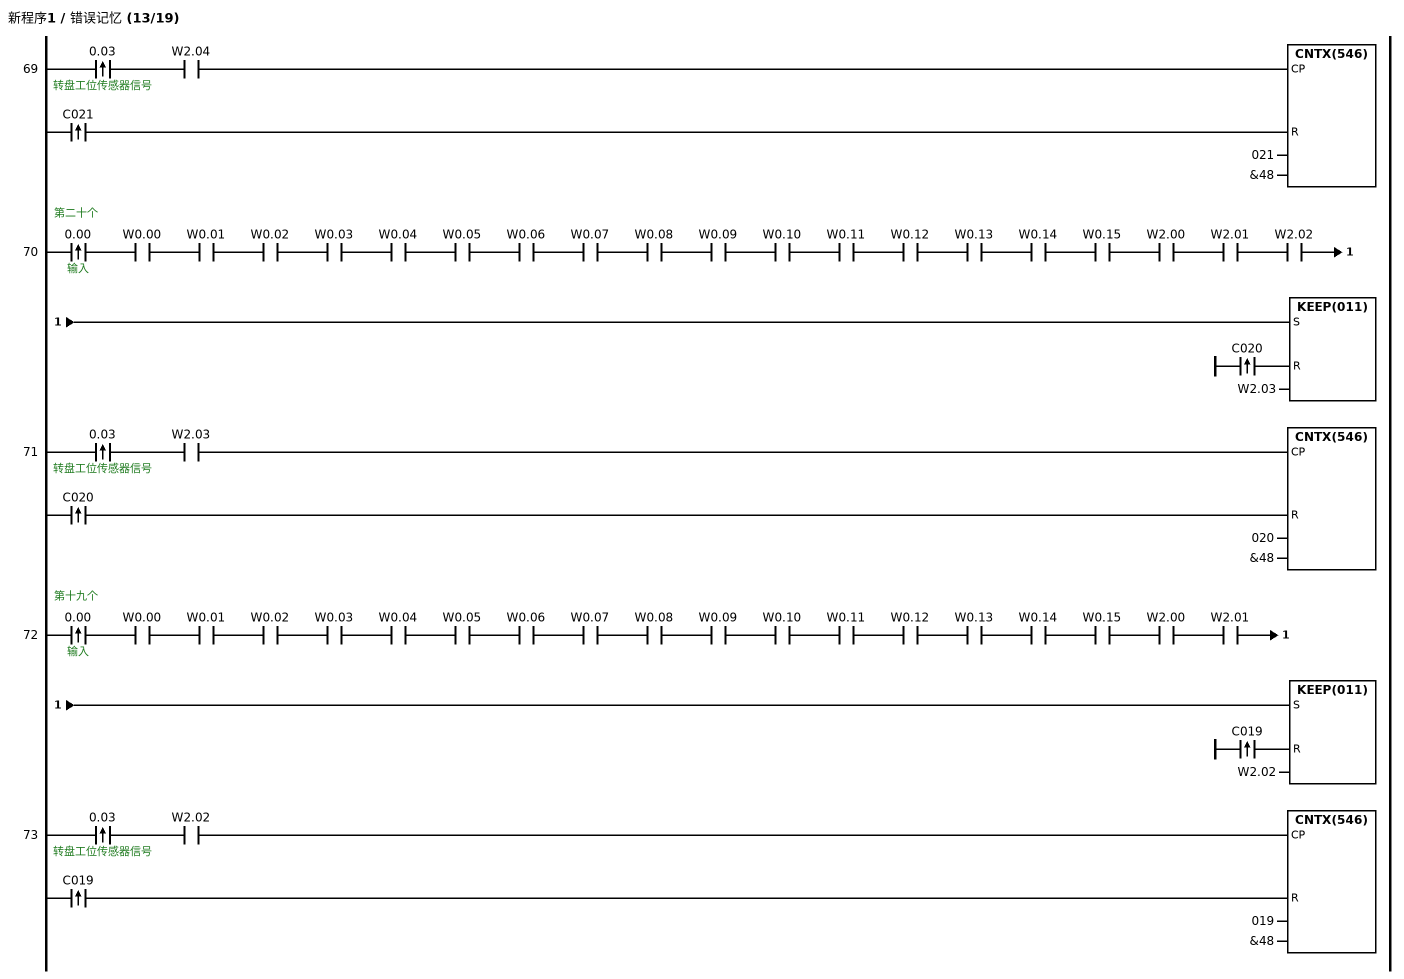
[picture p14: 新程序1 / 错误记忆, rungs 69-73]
; rung 69
@LD 0.03  ; 转盘工位传感器信号
AND W2.04
@LD C021
CNTX(546) 021 &48
; rung 70: 第二十个
@LD 0.00  ; 输入
AND W0.00
AND W0.01
AND W0.02
AND W0.03
AND W0.04
AND W0.05
AND W0.06
AND W0.07
AND W0.08
AND W0.09
AND W0.10
AND W0.11
AND W0.12
AND W0.13
AND W0.14
AND W0.15
AND W2.00
AND W2.01
AND W2.02
@LD C020
KEEP(011) W2.03
; rung 71
@LD 0.03  ; 转盘工位传感器信号
AND W2.03
@LD C020
CNTX(546) 020 &48
; rung 72: 第十九个
@LD 0.00  ; 输入
AND W0.00
AND W0.01
AND W0.02
AND W0.03
AND W0.04
AND W0.05
AND W0.06
AND W0.07
AND W0.08
AND W0.09
AND W0.10
AND W0.11
AND W0.12
AND W0.13
AND W0.14
AND W0.15
AND W2.00
AND W2.01
@LD C019
KEEP(011) W2.02
; rung 73
@LD 0.03  ; 转盘工位传感器信号
AND W2.02
@LD C019
CNTX(546) 019 &48

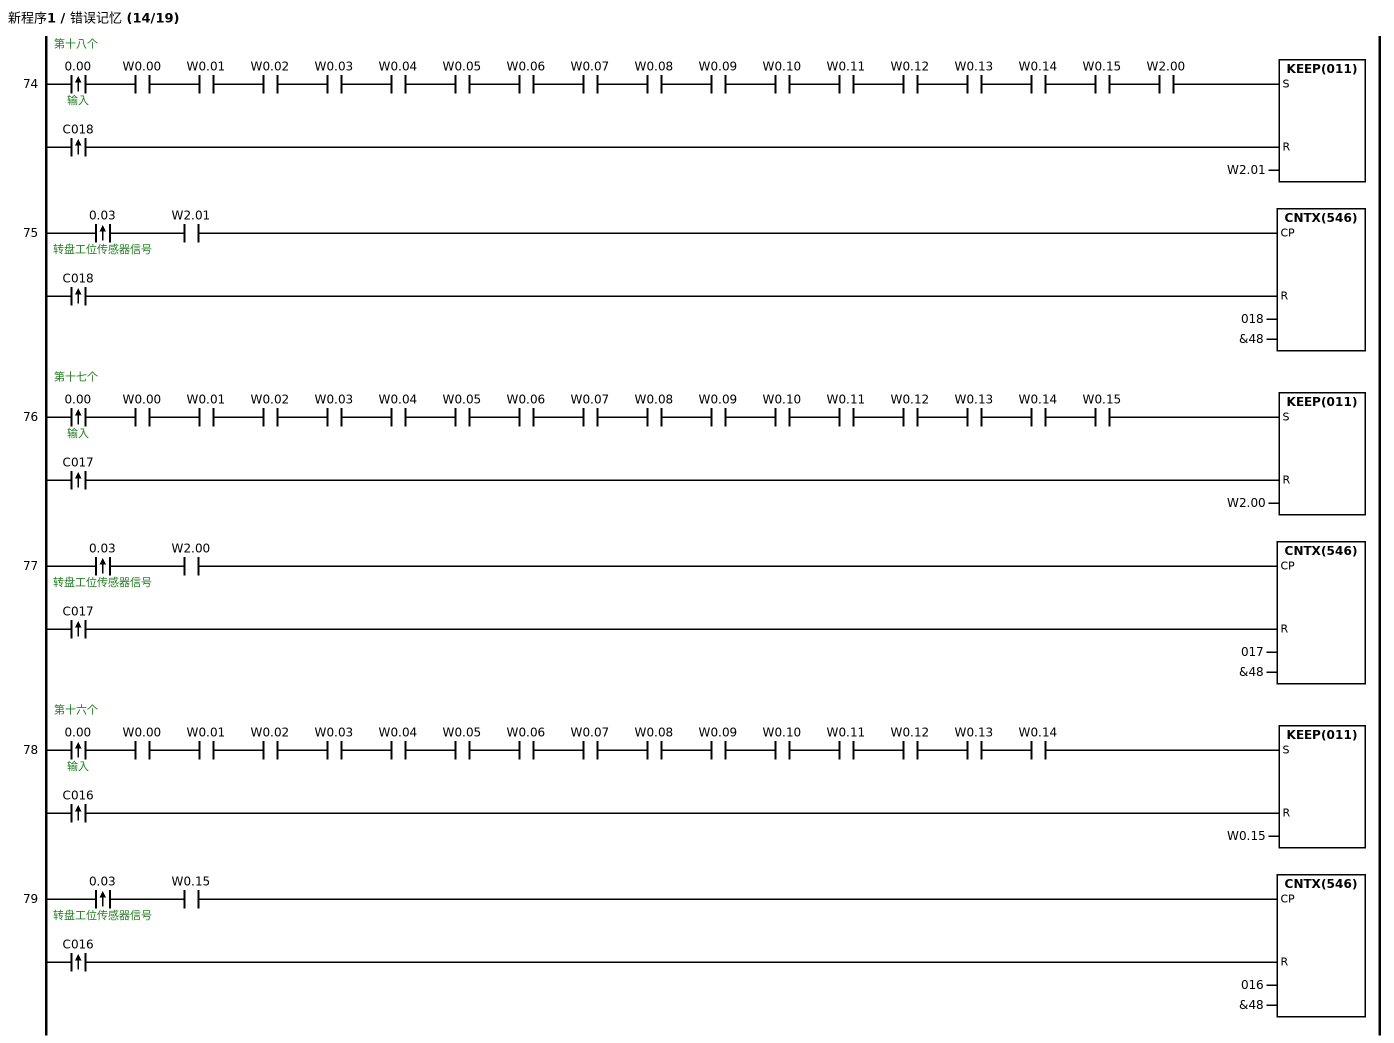
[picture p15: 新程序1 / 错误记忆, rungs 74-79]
; rung 74: 第十八个
@LD 0.00  ; 输入
AND W0.00
AND W0.01
AND W0.02
AND W0.03
AND W0.04
AND W0.05
AND W0.06
AND W0.07
AND W0.08
AND W0.09
AND W0.10
AND W0.11
AND W0.12
AND W0.13
AND W0.14
AND W0.15
AND W2.00
@LD C018
KEEP(011) W2.01
; rung 75
@LD 0.03  ; 转盘工位传感器信号
AND W2.01
@LD C018
CNTX(546) 018 &48
; rung 76: 第十七个
@LD 0.00  ; 输入
AND W0.00
AND W0.01
AND W0.02
AND W0.03
AND W0.04
AND W0.05
AND W0.06
AND W0.07
AND W0.08
AND W0.09
AND W0.10
AND W0.11
AND W0.12
AND W0.13
AND W0.14
AND W0.15
@LD C017
KEEP(011) W2.00
; rung 77
@LD 0.03  ; 转盘工位传感器信号
AND W2.00
@LD C017
CNTX(546) 017 &48
; rung 78: 第十六个
@LD 0.00  ; 输入
AND W0.00
AND W0.01
AND W0.02
AND W0.03
AND W0.04
AND W0.05
AND W0.06
AND W0.07
AND W0.08
AND W0.09
AND W0.10
AND W0.11
AND W0.12
AND W0.13
AND W0.14
@LD C016
KEEP(011) W0.15
; rung 79
@LD 0.03  ; 转盘工位传感器信号
AND W0.15
@LD C016
CNTX(546) 016 &48

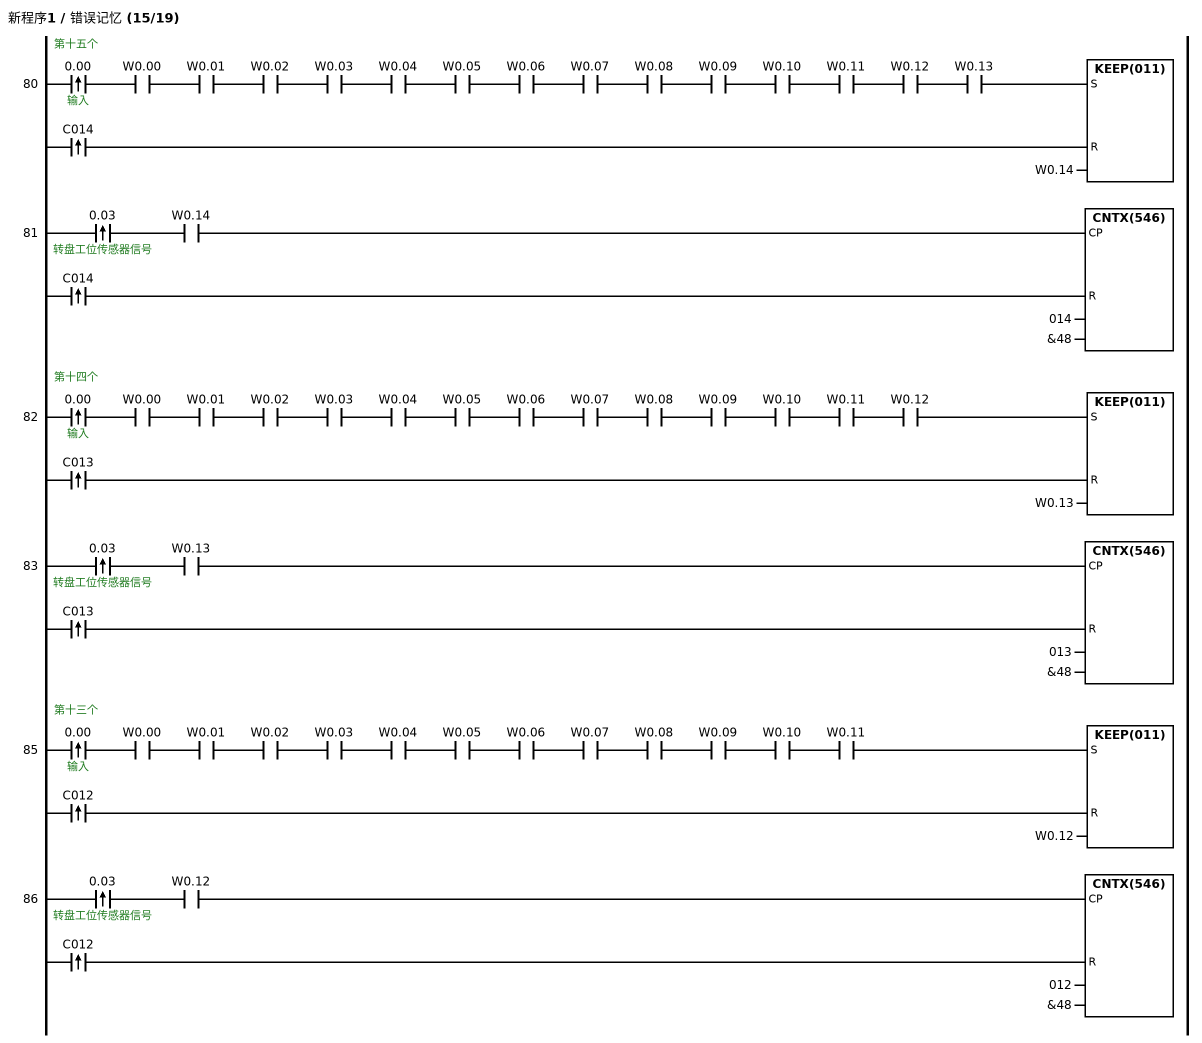
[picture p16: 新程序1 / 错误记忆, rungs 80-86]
; rung 80: 第十五个
@LD 0.00  ; 输入
AND W0.00
AND W0.01
AND W0.02
AND W0.03
AND W0.04
AND W0.05
AND W0.06
AND W0.07
AND W0.08
AND W0.09
AND W0.10
AND W0.11
AND W0.12
AND W0.13
@LD C014
KEEP(011) W0.14
; rung 81
@LD 0.03  ; 转盘工位传感器信号
AND W0.14
@LD C014
CNTX(546) 014 &48
; rung 82: 第十四个
@LD 0.00  ; 输入
AND W0.00
AND W0.01
AND W0.02
AND W0.03
AND W0.04
AND W0.05
AND W0.06
AND W0.07
AND W0.08
AND W0.09
AND W0.10
AND W0.11
AND W0.12
@LD C013
KEEP(011) W0.13
; rung 83
@LD 0.03  ; 转盘工位传感器信号
AND W0.13
@LD C013
CNTX(546) 013 &48
; rung 85: 第十三个
@LD 0.00  ; 输入
AND W0.00
AND W0.01
AND W0.02
AND W0.03
AND W0.04
AND W0.05
AND W0.06
AND W0.07
AND W0.08
AND W0.09
AND W0.10
AND W0.11
@LD C012
KEEP(011) W0.12
; rung 86
@LD 0.03  ; 转盘工位传感器信号
AND W0.12
@LD C012
CNTX(546) 012 &48

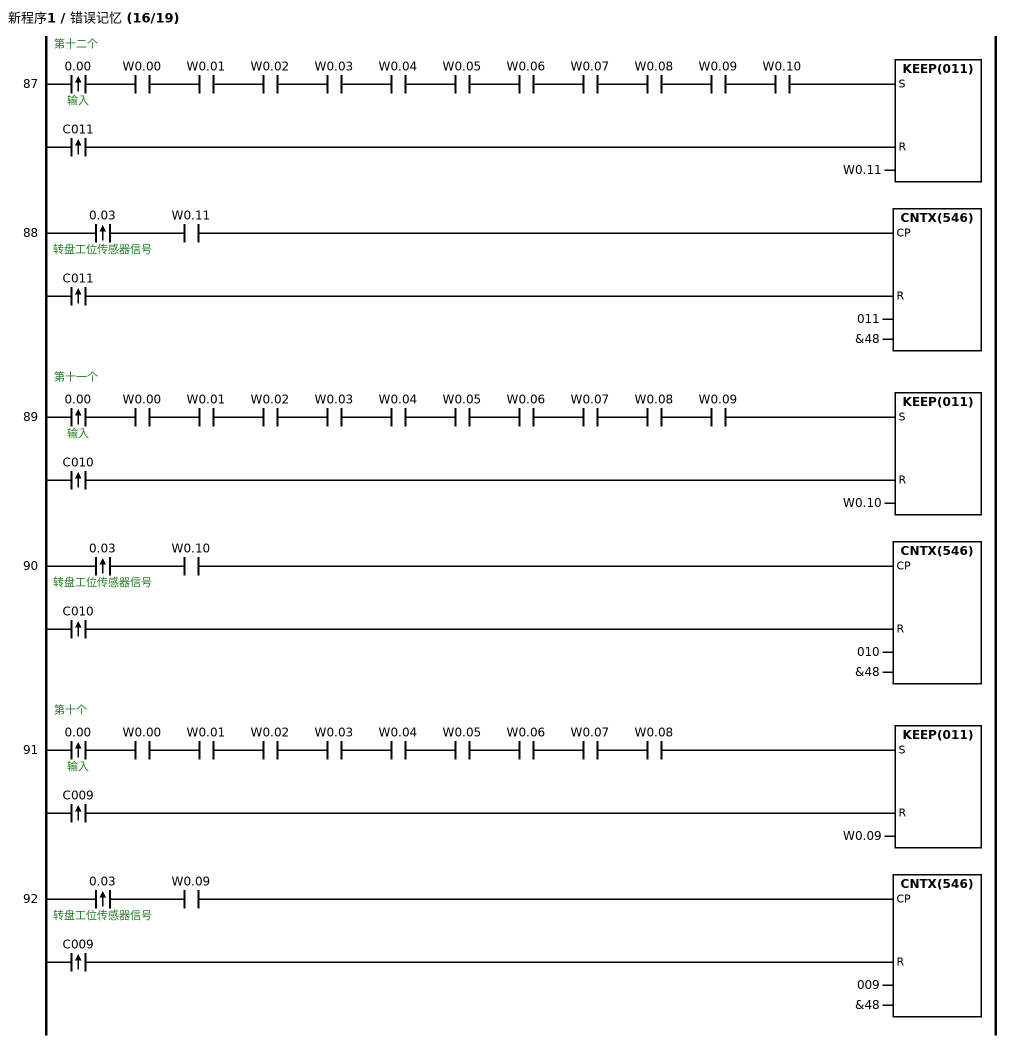
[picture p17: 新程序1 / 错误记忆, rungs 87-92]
; rung 87: 第十二个
@LD 0.00  ; 输入
AND W0.00
AND W0.01
AND W0.02
AND W0.03
AND W0.04
AND W0.05
AND W0.06
AND W0.07
AND W0.08
AND W0.09
AND W0.10
@LD C011
KEEP(011) W0.11
; rung 88
@LD 0.03  ; 转盘工位传感器信号
AND W0.11
@LD C011
CNTX(546) 011 &48
; rung 89: 第十一个
@LD 0.00  ; 输入
AND W0.00
AND W0.01
AND W0.02
AND W0.03
AND W0.04
AND W0.05
AND W0.06
AND W0.07
AND W0.08
AND W0.09
@LD C010
KEEP(011) W0.10
; rung 90
@LD 0.03  ; 转盘工位传感器信号
AND W0.10
@LD C010
CNTX(546) 010 &48
; rung 91: 第十个
@LD 0.00  ; 输入
AND W0.00
AND W0.01
AND W0.02
AND W0.03
AND W0.04
AND W0.05
AND W0.06
AND W0.07
AND W0.08
@LD C009
KEEP(011) W0.09
; rung 92
@LD 0.03  ; 转盘工位传感器信号
AND W0.09
@LD C009
CNTX(546) 009 &48

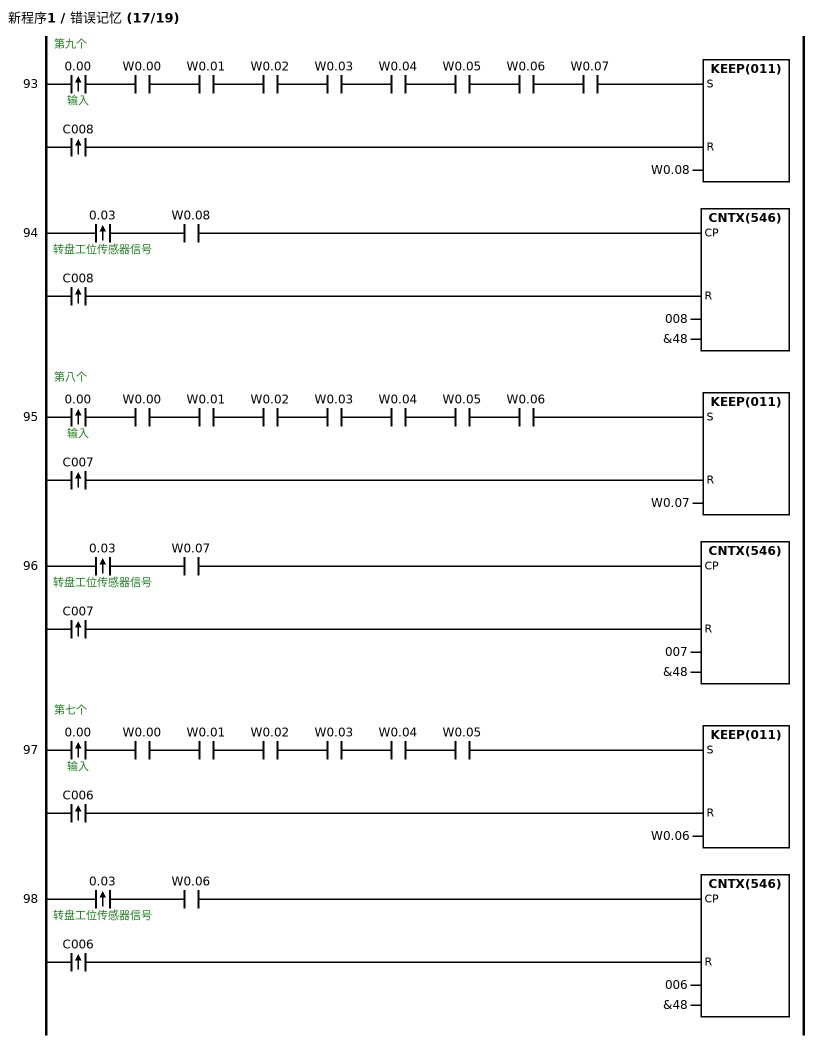
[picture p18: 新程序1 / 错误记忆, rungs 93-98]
; rung 93: 第九个
@LD 0.00  ; 输入
AND W0.00
AND W0.01
AND W0.02
AND W0.03
AND W0.04
AND W0.05
AND W0.06
AND W0.07
@LD C008
KEEP(011) W0.08
; rung 94
@LD 0.03  ; 转盘工位传感器信号
AND W0.08
@LD C008
CNTX(546) 008 &48
; rung 95: 第八个
@LD 0.00  ; 输入
AND W0.00
AND W0.01
AND W0.02
AND W0.03
AND W0.04
AND W0.05
AND W0.06
@LD C007
KEEP(011) W0.07
; rung 96
@LD 0.03  ; 转盘工位传感器信号
AND W0.07
@LD C007
CNTX(546) 007 &48
; rung 97: 第七个
@LD 0.00  ; 输入
AND W0.00
AND W0.01
AND W0.02
AND W0.03
AND W0.04
AND W0.05
@LD C006
KEEP(011) W0.06
; rung 98
@LD 0.03  ; 转盘工位传感器信号
AND W0.06
@LD C006
CNTX(546) 006 &48

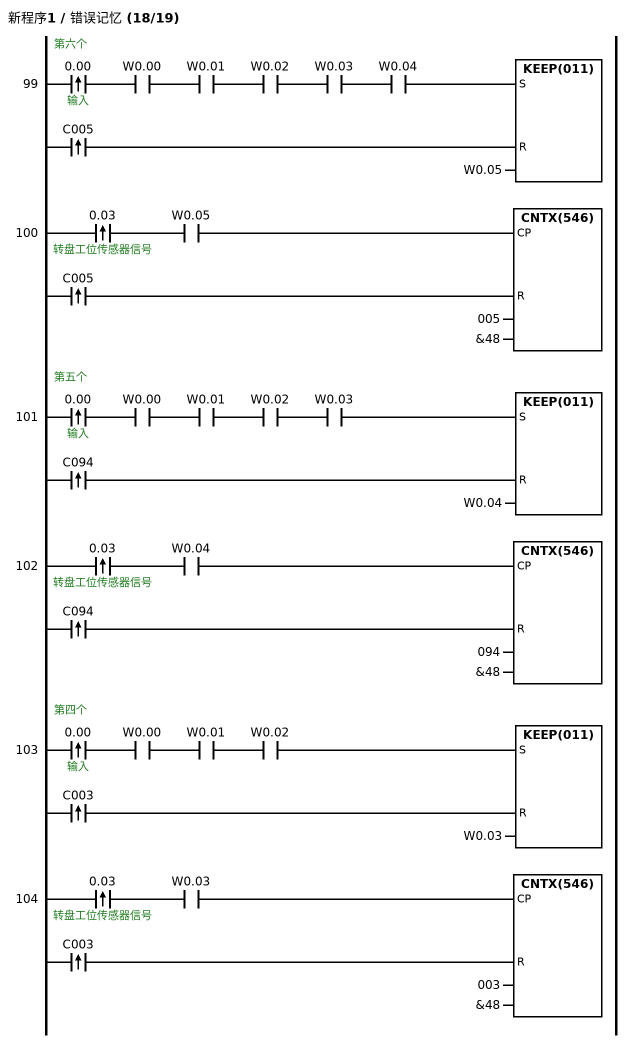
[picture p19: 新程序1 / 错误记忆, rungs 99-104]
; rung 99: 第六个
@LD 0.00  ; 输入
AND W0.00
AND W0.01
AND W0.02
AND W0.03
AND W0.04
@LD C005
KEEP(011) W0.05
; rung 100
@LD 0.03  ; 转盘工位传感器信号
AND W0.05
@LD C005
CNTX(546) 005 &48
; rung 101: 第五个
@LD 0.00  ; 输入
AND W0.00
AND W0.01
AND W0.02
AND W0.03
@LD C094
KEEP(011) W0.04
; rung 102
@LD 0.03  ; 转盘工位传感器信号
AND W0.04
@LD C094
CNTX(546) 094 &48
; rung 103: 第四个
@LD 0.00  ; 输入
AND W0.00
AND W0.01
AND W0.02
@LD C003
KEEP(011) W0.03
; rung 104
@LD 0.03  ; 转盘工位传感器信号
AND W0.03
@LD C003
CNTX(546) 003 &48

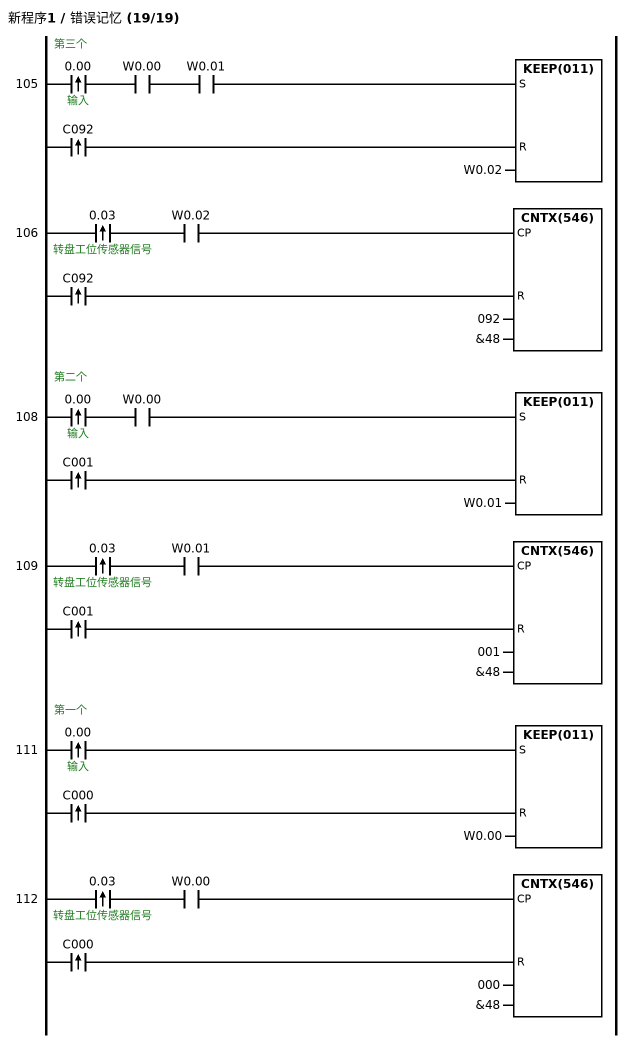
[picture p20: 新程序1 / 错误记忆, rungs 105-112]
; rung 105: 第三个
@LD 0.00  ; 输入
AND W0.00
AND W0.01
@LD C092
KEEP(011) W0.02
; rung 106
@LD 0.03  ; 转盘工位传感器信号
AND W0.02
@LD C092
CNTX(546) 092 &48
; rung 108: 第二个
@LD 0.00  ; 输入
AND W0.00
@LD C001
KEEP(011) W0.01
; rung 109
@LD 0.03  ; 转盘工位传感器信号
AND W0.01
@LD C001
CNTX(546) 001 &48
; rung 111: 第一个
@LD 0.00  ; 输入
@LD C000
KEEP(011) W0.00
; rung 112
@LD 0.03  ; 转盘工位传感器信号
AND W0.00
@LD C000
CNTX(546) 000 &48

### Section 剔除

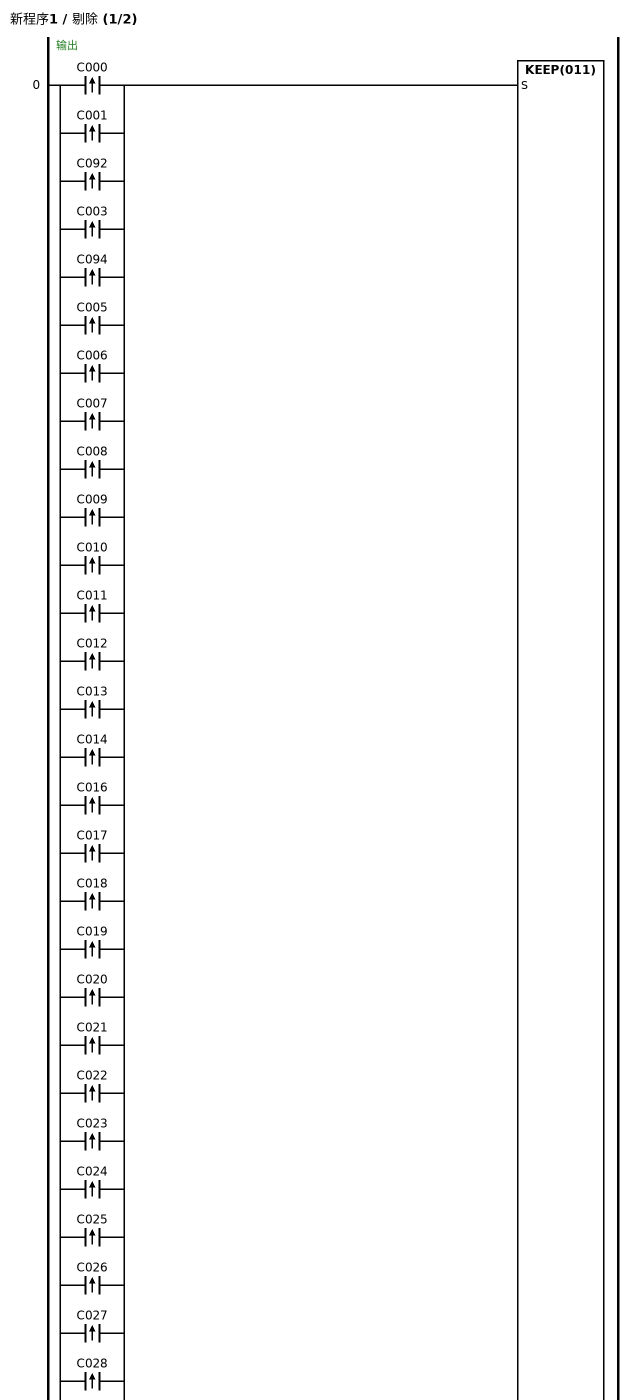
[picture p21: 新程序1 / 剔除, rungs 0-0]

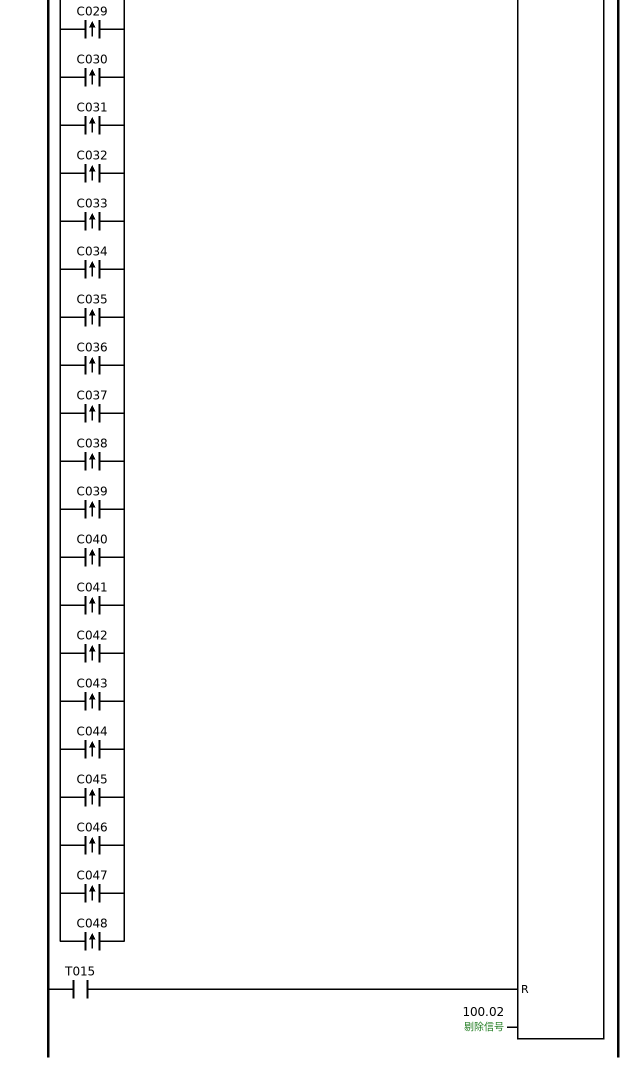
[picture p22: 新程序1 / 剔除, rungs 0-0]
; rung 0: 输出
@LD C000
@OR C001
@OR C092
@OR C003
@OR C094
@OR C005
@OR C006
@OR C007
@OR C008
@OR C009
@OR C010
@OR C011
@OR C012
@OR C013
@OR C014
@OR C016
@OR C017
@OR C018
@OR C019
@OR C020
@OR C021
@OR C022
@OR C023
@OR C024
@OR C025
@OR C026
@OR C027
@OR C028
@OR C029
@OR C030
@OR C031
@OR C032
@OR C033
@OR C034
@OR C035
@OR C036
@OR C037
@OR C038
@OR C039
@OR C040
@OR C041
@OR C042
@OR C043
@OR C044
@OR C045
@OR C046
@OR C047
@OR C048
LD T015
KEEP(011) 100.02  ; 剔除信号

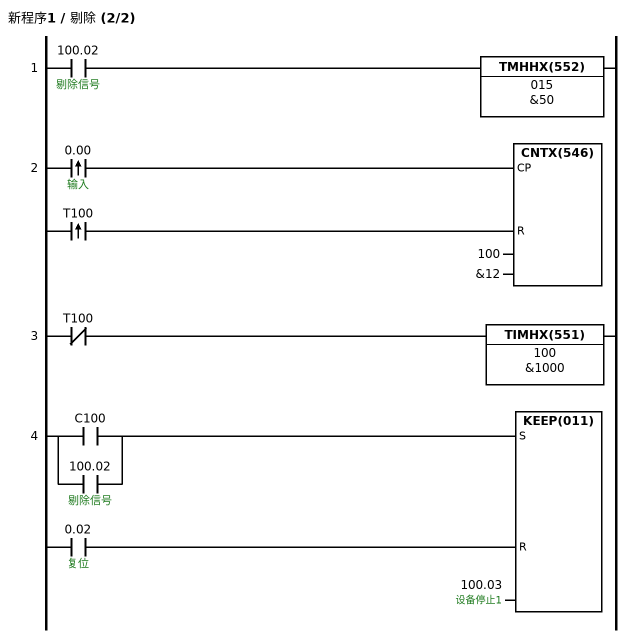
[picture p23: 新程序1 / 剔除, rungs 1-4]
; rung 1
LD 100.02  ; 剔除信号
TMHHX(552) 015 &50
; rung 2
@LD 0.00  ; 输入
@LD T100
CNTX(546) 100 &12
; rung 3
LDNOT T100
TIMHX(551) 100 &1000
; rung 4
LD C100
OR 100.02  ; 剔除信号
LD 0.02  ; 复位
KEEP(011) 100.03  ; 设备停止1

### Section END
; rung 0
END(001)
